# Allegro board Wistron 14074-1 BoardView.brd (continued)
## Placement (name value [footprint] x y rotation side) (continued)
R9731  0R0402-PAD-2-GP  [0R0402-PAD-1]  54.86 47.88 180 top
R9732  10KR2J-3-GP  [R402H16]  4.93 69.04 0 bottom
R9733  2K2R2J-2-GP  [R402H16]  4.93 70.94 180 bottom
R9734  2K2R2J-2-GP  [R402H16]  5.13 56.87 270 bottom
R9735  10KR2J-3-GP  [R402H16]  7.04 56.87 90 bottom
R9736  0R0402-PAD-2-GP  [0R0402-PAD-1]  24 88.14 180 top
R9737  0R2J-2-GP  [R402H16]  22.86 88.14 180 top
R9739  1KR2J-1-GP  [R402H16]  4.83 47.37 0 bottom
R9740  1KR2J-1-GP  [R402H16]  4.7 43.31 180 bottom
R9741  10KR2J-3-GP  [R402H16]  5.46 38.48 180 bottom
R9742  56D2R2F-GP  [R402H16]  135.36 139.45 0 top
R9743  56D2R2F-GP  [R402H16]  135.48 137.41 180 top
R9744  200R2F-L-GP  [R402H16]  132.21 142.27 180 bottom
R9745  200R2F-L-GP  [R402H16]  131.04 142.27 180 bottom
R9746  200R2F-L-GP  [R402H16]  39.19 69.72 270 bottom
R9751  200R2F-L-GP  [R402H16]  130.76 139.12 0 bottom
R9753  49D9R2F-GP  [R402H16]  130.07 137.59 270 bottom
R9754  49D9R2F-GP  [R402H16]  38.84 70.94 270 bottom
R9755  301R2F-GP  [R402H16]  132.21 142.62 0 top
R9756  20R2F-GP  [R402H16]  133.25 142.65 0 top
R9757  20R2F-GP  [R402H16]  37.9 65.41 90 bottom
R9761  10KR2F-2-GP  [R402H16]  182.96 64.47 270 bottom
R9762  10KR2F-2-GP  [R402H16]  189.98 68.14 90 bottom
R9764  0R0402-PAD-2-GP  [0R0402-PAD-1]  187.29 58.61 0 bottom
R9765  0R0402-PAD-2-GP  [0R0402-PAD-1]  188.33 58.61 180 bottom
R9766  10KR2F-2-GP  [R402H16]  187.62 64.53 90 bottom
R9767  10KR2F-2-GP  [R402H16]  189.73 66.05 0 bottom
R9768  10KR2F-2-GP  [R402H16]  186.14 58.64 0 bottom
R9769  10KR2F-2-GP  [R402H16]  190.74 63.39 90 bottom
R9770  10KR2F-2-GP  [R402H16]  182.85 58.65 0 bottom
R9771  10KR2F-2-GP  [R402H16]  184.84 64.47 90 bottom
R9772  0R2J-2-GP  [R402H16]  183.9 58.64 0 bottom
R9773  0R0402-PAD-2-GP  [0R0402-PAD-1]  184.91 58.64 0 bottom
R9786  100KR2J-1-GP  [R402H16]  189.52 58.61 0 bottom
R9787  0R0402-PAD-2-GP  [0R0402-PAD-1]  91.44 91.8 135 bottom
R9788  2K2R2J-2-GP  [R402H16]  5.71 115.95 0 bottom
R9789  10KR2J-3-GP  [R402H16]  6.73 115.95 0 bottom
R9790  10KR2J-3-GP  [R402H16]  6.58 109.5 270 bottom
R9792  2K2R2J-2-GP  [R402H16]  5.18 62.2 270 bottom
R9793  10KR2J-3-GP  [R402H16]  8.13 61.59 0 bottom
R9794  0R3J-0-U-GP  [R603H22]  11.78 133.26 270 top
R9795  0R3J-0-U-GP  [R603H22]  11.8 135.24 270 top
R9796  0R3J-0-U-GP  [R603H22]  11.81 139.13 270 top
R9797  0R3J-0-U-GP  [R603H22]  11.81 137.17 270 top
R9798  0R0603-PAD-2-GP-U  [0R0603-PAD-1-U]  13.57 144.24 270 top
R9799  0R0603-PAD-2-GP-U  [0R0603-PAD-1-U]  13.6 150.59 270 top
R9800  0R0603-PAD-2-GP-U  [0R0603-PAD-1-U]  21.84 134.37 270 top
R9801  0R0603-PAD-2-GP-U  [0R0603-PAD-1-U]  37.97 141.72 180 top
R9809  0R2J-2-GP  [R402H16]  180.21 146.05 270 top
R9810  0R2J-2-GP  [R402H16]  180.21 147.19 270 top
R9811  10KR2J-3-GP  [R402H16]  183.59 144.78 180 bottom
R9812  10KR2J-3-GP  [R402H16]  182.55 152.78 0 bottom
R9813  10KR2J-3-GP  [R402H16]  179.63 152.78 0 bottom
R9814  10KR2J-3-GP  [R402H16]  180.64 152.78 0 bottom
R9815  0R2J-2-GP  [R402H16]  116.52 27.73 90 bottom
R9816  0R2J-2-GP  [R402H16]  114.76 27.05 90 top
R9817  0R0402-PAD-2-GP  [0R0402-PAD-1]  45.11 122.28 180 bottom
R9818  2K2R2J-2-GP  [R402H16]  7.87 115.82 180 bottom
R9828  0R2J-2-GP  [R402H16]  21.44 33.15 90 top
R9829  0R0402-PAD-2-GP  [0R0402-PAD-1]  21.44 34.19 90 top
R9830  0R2J-2-GP  [R402H16]  22.61 28.07 180 top
R9831  0R2J-2-GP  [R402H16]  21.21 28.07 180 top
R9836  10KR2J-3-GP  [R402H16]  123.32 155.7 90 bottom
R9837  10KR2J-3-GP  [R402H16]  127 153.42 90 bottom
R9838  10KR2J-3-GP  [R402H16]  127.51 152.27 90 bottom
R9839  10KR2J-3-GP  [R402H16]  127.51 151.13 90 bottom
R9842  100KR2J-1-GP  [R402H16]  4.6 124.33 180 bottom
R9843  10KR2F-2-GP  [R402H16]  4.6 120.27 180 bottom
R9845  0R2J-2-GP  [R402H16]  16.64 13.21 0 top
R9846  1KR2J-1-GP  [R402H16]  24.94 79.25 180 top
R9847  10KR2J-3-GP  [R402H16]  26.16 84.76 270 top
R9848  2K2R2J-2-GP  [R402H16]  28.09 82.7 270 top
R9849  1KR2J-1-GP  [R402H16]  8.26 108.08 0 top
R9850  10KR2J-3-GP  [R402H16]  6.99 103.76 90 top
R9851  2K2R2J-2-GP  [R402H16]  5.08 103.76 270 top
R9852  10KR2J-3-GP  [R402H16]  95.1 76.3 135 bottom
R9853  0R2J-2-GP  [R402H16]  24.94 81.15 180 top
R9854  0R2J-2-GP  [R402H16]  8.26 106.17 0 top
R9855  1KR2J-1-GP  [R402H16]  91.39 85.1 90 bottom
R9857  0R0402-PAD-2-GP  [0R0402-PAD-1]  26.16 83.74 270 top
R9858  0R2J-2-GP  [R402H16]  26.16 82.73 270 top
R9859  1KR2J-1-GP  [R402H16]  44.2 127.74 180 bottom
R9861  10KR2J-3-GP  [R402H16]  27.61 84.15 180 top
R9863  150R2F-1-GP  [R402H16]  117.09 102.64 135 bottom
R9864  10KR2J-3-GP  [R402H16]  112.27 111.25 225 top
R9866  0R2J-2-GP  [R402H16]  177.8 145.16 0 top
R9867  20KR2J-L2-GP  [R402H16]  101.45 117.91 315 top
R9872  2K2R2J-2-GP  [R402H16]  7.75 71.12 90 bottom
R9873  200R2F-L-GP  [R402H16]  39.12 67.46 270 bottom
R9874  301R2F-GP  [R402H16]  39.12 66.45 270 bottom
R9875  0R0402-PAD-2-GP  [0R0402-PAD-1]  134.34 142.65 180 top
R9876  0R0402-PAD-2-GP  [0R0402-PAD-1]  131.5 144.22 270 top
R9879  10KR2J-3-GP  [R402H16]  176.81 143.59 180 bottom
R9882  8K2R2J-3-GP  [R402H16]  98.53 31.14 270 bottom
R9884  0R2J-2-GP  [R402H16]  31.62 12.95 270 top
RN801  SRN2K2J-1-GP  [ARES2H16]  159 149.99 270 top
RN1501  SRN2K2J-1-GP  [ARES2H16]  157.96 127.38 270 bottom
RN1502  SRN2K2J-1-GP  [ARES2H16]  33.37 140.75 270 top
RN1503  SRN2K2J-1-GP  [ARES2H16]  174.75 145.03 90 bottom
RN1901  SRN2K2J-1-GP  [ARES2H16]  27.79 86.54 270 top
RN1902  SRN2K2J-1-GP  [ARES2H16]  49.02 124.97 180 bottom
RN1903  SRN2K2J-1-GP  [ARES2H16]  80.14 41.12 180 top
RN2501  SRN4K7J-8-GP  [SMD-ARES4H18]  77.08 49.46 90 bottom
RN2502  SRN4K7J-8-GP  [SMD-ARES4H18]  77.05 51.51 90 bottom
RN3601  SRN2K2J-5-GP  [SMD-ARES4H18]  48.24 102.07 90 top
RN5402  SRN2K2J-1-GP  [ARES2H16]  134.82 150.67 0 top
RN5404  SRN2K2J-5-GP  [SMD-ARES4H18]  45.67 101.68 0 top
RN5407  SRN2K2J-1-GP  [ARES2H16]  8.64 54.36 180 bottom
RN5408  SRN10KJ-5-GP  [ARES2H18]  8.15 58.95 0 bottom
RN5409  SRN2K2J-1-GP  [ARES2H16]  8.38 64.64 0 bottom
RN5410  SRN10KJ-6-GP  [ARES8-CN24-MUH20]  109.04 18.92 0 bottom
RN5411  SRN2K2J-1-GP  [ARES2H16]  66.1 125.21 0 bottom
RN5601  SRN1KJ-7-GP  [SMD-ARES4H18]  155.96 147.96 270 top
RN5602  SRN1KJ-7-GP  [SMD-ARES4H18]  159 147.96 90 top
RN5603  SRN1KJ-7-GP  [SMD-ARES4H18]  124.51 152.02 270 bottom
RN5604  SRN1KJ-7-GP  [SMD-ARES4H18]  124.51 154.03 270 bottom
RN6102  SRN0J-6-GP  [SMD-ARES4H20]  28.07 113.54 0 bottom
RN6401  SRN1KJ-7-GP  [SMD-ARES4H18]  8.69 26.04 0 bottom
RN9901  SRN0J-6-GP  [SMD-ARES4H20]  192.15 119.38 0 bottom
SATA0  SKT-SATA7P-19-GP-U  [ABA-SAT-010-K04-U]  55 13 90 top
SATA1  SKT-SATA7P-19-GP-U  [ABA-SAT-010-K04-U]  64.45 13 90 top
SATAP1  JWT-CON6-3-GP  [A2501WV2-6P]  24.15 45.76 270 top
SIO1  IT8772E-EX-GP  [LQFP64H63]  106.81 28.03 180 bottom
SPI1  SKT-SPI8P-GP-U1  [SKT-SOIC8-092117H235]  75.93 52.5 0 top
SPIH1  PIN-CON3-S-GP  [21S-91-03GB01]  73.71 38.63 90 top
TC1901  E220U16VM-25-GP  [ECAP-100D6D3H473]  26.42 126.54 0 top
TC2201  SC10U6D3V3MX-GP  [C603H38]  28.5 155.22 0 top
TC2202  SC10U6D3V3MX-GP  [C603H38]  26.41 155.24 0 top
TC2203  E100U16VM-25-GP  [ECAP-80D5H493]  5.41 152.48 90 top
TC2204  E100U16VM-25-GP  [ECAP-80D5H493]  9.48 146.64 90 top
TC2501  E220U16VM-25-GP  [ECAP-100D6D3H473]  189.59 32.05 90 top
TC2701  E100U16VM-25-GP  [ECAP-80D5H493]  37.21 146.56 90 top
TC2702  SC10U6D3V3MX-GP  [C603H38]  27.23 162.02 90 top
TC2703  SC10U6D3V3MX-GP  [C603H38]  27.24 163.97 90 top
TC2704  E100U16VM-25-GP  [ECAP-80D5H493]  30.61 146.56 90 top
TC2705  SC10U6D3V3MX-GP  [C603H38]  27.24 158.12 90 top
TC2706  SC10U6D3V3MX-GP  [C603H38]  27.24 160.07 90 top
TC4601  SC10U10V5KX-2GP  [C805H54]  36.47 110.39 90 bottom
TC4602  E220U16VM-25-GP  [ECAP-100D6D3H473]  92.58 146.18 0 top
TC4603  E220U16VM-25-GP  [ECAP-100D6D3H473]  33.47 29.59 0 top
TC4606  E220U16VM-25-GP  [ECAP-100D6D3H473]  106.81 144.17 0 top
TP2401  -  [TPAD28]  112.9 28.32 180 bottom
TP2402  -  [TPAD28]  114.33 27.37 180 bottom
TP9601  TPAD14-OP-GP  [TPAD14-OP]  190.12 104.62 0 bottom
TP9602  TPAD14-OP-GP  [TPAD14-OP]  190.12 105.89 0 bottom
TP9905  -  [TPAD24]  137.34 89.15 0 top
TP9906  -  [TPAD24]  90.42 92.35 0 top
TXE1  PIN-CON3-S-GP  [21S-91-03GB01]  175.69 133.19 270 top
U3RJ1  SKT-RJ45-USB-83-GP  [PU2B1B5-PRTB]  76.9 163.99 180 top
U2402  G2129TL1U-GP  [SC70-6H44]  116.21 35.14 270 bottom
U2502  W25Q64FWSSIG-GP  [SOIC8-1H86]  75.93 52.5 180 top
U2901  GS7605ST-R-GP  [SOT23-8PH36]  25.5 30.35 270 top
U2903  GS7605ST-R-GP  [SOT23-8PH36]  25.4 34.54 270 top
U3701  SY6288CAAC-GP  [SOT-23-5H56]  25.4 34.29 270 bottom
U3702  SY6288CAAC-GP  [SOT-23-5H56]  107.92 150.42 0 top
U3703  SY6288CAAC-GP  [SOT-23-5H56]  25.53 30.48 270 bottom
U3801  SY6288CAAC-GP  [SOT-23-5H56]  113.03 154.43 270 bottom
U4301  AO4468L-GP  [SOIC8H69]  173.61 17.91 270 top
U4601  GL850G-OHY31-GP  [QFN28-G3D75H32]  42.57 101.48 90 bottom
U4602  M24C02-WMN6TP-1-GP  [SOIC8H69]  42.42 112.98 0 bottom
U5401  TPS22966DPUR-GP  [SON14J3020-G2610H34]  158.35 19.91 270 top
U6506  RTD2168-CGT-GP  [QFN32-G3D6H40]  174.68 149.79 270 top
U6510  GS7605ST-R-GP  [SOT23-8PH36]  119.89 156.21 270 bottom
U6511  GS7605ST-R-GP  [SOT23-8PH36]  118.62 152.27 270 bottom
U6519  M24128-BWMN6TP-GP  [SOIC8H69]  165.2 149.63 180 top
U6523  2N7002KDW-1-GP  [SOT-363H44]  188.2 62.13 0 bottom
U6524  2N7002KDW-1-GP  [SOT-363H44]  184.01 62.13 0 bottom
UART1  JOWLE-CON2-5-GP  [A2541WV0-1EX2PA-6T]  73.73 31.45 270 top
USB2F1  PIN-CON5-SFP2-GP-U  [210-91-05GY21-U]  47.5 11 270 top
USB2F2  JWT-CONN10D-SFP10-GP  [A2541WV0-2AX5PA-6T-K]  34.37 45.26 90 top
USB2R1  SKT-USB12-24-GP  [SKT-USB12-157183]  99.4 160.72 180 top
USB3F1  LOTES-CONN20C-SFP1-GP  [ABA-USB-050-K07]  41.5 36 90 top
VGA1  D-SUB-15-154-GP  [DZ11AA1-H5W7-4F]  166 166 0 top
X1501  XTAL-19D2MHZ-12-GP  [OSC-3225-4P-4H30]  94.33 101.48 45 top
X2101  XTAL-25MHZ-181-GP  [OSC-3225-4P-4H36]  60.47 119.92 90 top
X3501  XTAL-12MHZ-67-GP  [OSC-3225-4P-4H36]  47.47 97.44 270 top
X3502  XTAL-32D768KHZ-64-GP  [SMD49-6914-0403H56]  89.12 98.03 135 top
XDP1  SMC-CONN60A-GP  [BSH-03001-FDA]  186.99 105.03 90 bottom

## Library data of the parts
ATX1 = C4201WV0-B2X12P: tolerance: 21.70163.212
ATX2 = PPA12635GD210F: tolerance: 20.80334.020
AUDH1 = 1E450400: tolerance: 21.62868.205
AUDIO1 = PFPCC48-1H63: tolerance: 71.00662.00G
AUDR1 = ABA-JAK-028-K03: tolerance: 22.10251.831
BT1 = AAA-BAT-029-K01: tolerance: 22.70034.011
BUZ1 = AC-1205G-N1LF-U: tolerance: 23.60026.001
C20 C501-C504 C1217 C1218 C1225 C1226 C1315 C1317 C1318 C1325 C1326 C1801 C1802 C1903 C1905-C1913 C2002 C2006 C2009 C2011-C2014 C2016 C2019 C2020 C2103-C2105 C2107-C2111 C2115 C2201 C2203 C2205 C2207 C2208 C2211 C2215-C2217 C2219 C2301 C2415 C2434 C2435 C2501 C2507 C2709 C2813 C3402 C3405 C3407 C3408 C3410 C3501 C3508 C3509 C4601 C4605 C4606 C4608 C4610 C5401-C5410 C7542 C9602-C9604 C9606 C15110 C15112-C15127 C15141-C15146 C15149-C15152 C15154 C15155 C15157 C15163-C15167 C15170-C15175 C15186 C15188 C15191 C15192 EC3401 EC3412-EC3414 PC3602 PC4202 PC4203 PC4410 PC4416 PC4428 PC4510 PC4516 PC4528 PC4701 PC4707 PC4803 PC4808 PC5003 PC5029 PC5032 PC5103 PC5109 PC5212 PC5218 PC5219 = C402H22: tolerance: 78.10421.2FL
C1001-C1008 C1013 C1017 C1018 C1020 C1022 C1024-C1027 C1030 C1032-C1035 C1037 C1047 C1056 C1057 C1102 C1103 C1105 C1108 C1110 C1111 C1113 C1115 C1116 C1118 C1119 C1121 C1126-C1128 C1132-C1134 C1137 C1138 C1209-C1216 C1219-C1222 C1309-C1314 C1316 C1319-C1322 C2003 C2008 C2017 C2040 C2114 C2503 C2912 C3502 C3505 C4602 C4607 C4609 C5416 C5418 C15111 C15185 C15187 C15189 C15190 PC4422 PC4522 PC4702 PC4802 PC4909 PC4910 PC4926 PC5028 PC5034 PC5035 PC5104 PC5112 PC5213 = C402H22: tolerance: 78.10523.5FL
C1009-C1012 C1040-C1042 C1048 C1104 C1114 C1120 C1122-C1124 C1130 C2707 C5413 C5415 C5417 C5419 = C603H40: tolerance: 78.22610.5BL
C1031 C1043-C1046 C1049 C1201-C1208 C1223 C1224 C1230 C1231 C1301-C1308 C1323 C1324 C1330 C1331 C2506 C6102 C15147 C15148 PC4708 PC4804 PC4806 PC4807 PC5031 PC5108 PC5214 PC5216 PC5217 TC2201 TC2202 TC2702 TC2703 TC2705 TC2706 = C603H38: tolerance: 78.10610.5BL
C1227 C1327 C2229 C2907 C2908 C3301 C3302 C3403 PC4413 PC4418 PC4429 PC4513 PC4518 PC4529 PC4704 PC5005 PC5041 = C402H22: tolerance: 78.10224.2FL
C1412 C1413 C1417-C1422 C4303 PC4427 PC4527 PC4922 PC4923 PC4925 PC5002 = C402H22: tolerance: 78.10324.2FL
C1501 C1502 = C402H22: tolerance: 78.6R874.1FL
C1803 C2206 EC7615-EC7617 PC4705 PC4805 PC5107 PC5215 = C402H22: tolerance: 78.22034.1FL
C1901 C1902 C2015 C2018 C2101 C2708 C2809-C2811 C2903 C2911 C3411 C3416 C5601-C5604 C15129 C15183 C15184 EC3409 = C402H22: tolerance: 78.10491.4FL
C2001 C2005 C2227 C2228 C2230 C2231 C2701-C2706 C5303 C5306 EC2314 EC2323 EC7612 EC7613 PC4206 = C402H22: tolerance: 78.10134.1FL
C2004 C2102 C2106 C3404 = C402-TO0D2H26: tolerance: 78.47510.5FL
C2010 C3504 C3506 C3507 = C603H36: tolerance: 78.10593.4BL
C2116 C2117 = C402H22: tolerance: 78.15034.1FL
C2119 C2120 PC4914 PC4918 = C603H36: tolerance: 78.47520.5BL
C2202 C2204 PC3601 PC3603 = C805H54: tolerance: 78.10693.41L
C2209 C2212 C2218 C2220 TC4601 = C805H54: tolerance: 78.10623.51L
C2210 EC2501-EC2503 = C402H22: tolerance: 78.4R774.1FL
C2303 PC4417 PC4419 PC4517 PC4519 = C402H22: tolerance: 78.47124.2FL
C3406 = C402H22: tolerance: 78.10322.2FL
C4301 C6001 C6002 PC4201 PC4908 PC4921 PC4927 PC5004 = C603H36: tolerance: 78.10422.2BL
C4302 C5001 C5411 EC4101 PC4204 PC4703 PC5011 PC5040 PC5105 = C603H36: tolerance: 78.10424.2BL
C4603 C4604 = C402H24: tolerance: 78.12034.1FL
C4611 = C603H36: tolerance: 78.10421.2BL
C5301 C5307-C5311 = C402H22: tolerance: 78.4R7B4.1FL
C5304 C5305 = C402H22: tolerance: 78.18034.1FL
C5412 C5414 = C402H22: tolerance: 78.10224.L1L
C6003 C6004 PC4424 PC4431 PC4524 PC4531 PC4706 PC4711 PC5038 PC5039 PC5101 PC5102 = C805H56: tolerance: 78.10622.51L
C6101 C6103 C6104 = C402H22: tolerance: 78.10422.2FL
C6105 = C402H22: tolerance: 78.10034.1FL
C7537 C7539 = C402H22: tolerance: 78.10523.L2L
C7538 C7540 = C402H22: tolerance: 78.7R064.1FL
C7924 EC4102 PC4423 PC4523 = C402H22: tolerance: 78.10422.5FL
C9605 PC5036 PC5037 = C402H22: tolerance: 78.10423.2FL
C15153 C15156 PC4426 PC4526 = C603H36: tolerance: 78.22523.5BL
C15178 PC4801 PC5211 PC5220-PC5222 = C402H20: tolerance: 78.10423.5FL
CMOS1 SPIH1 TXE1 = 21S-91-03GB01: tolerance: 21.61445.103
CPU1 = BGA1170M2725H57: tolerance: 071.BRASW.000U
D3 D4 = SOT-23-9H44: tolerance: 83.00056.Q11
D1501 = SOT23-2D4-312H44: tolerance: 75.00054.T7D
D2101 D2402 D2502 D3401 = SOD323AKH40: tolerance: 83.00355.F1F
D2201 D2203 = SOT-23-10H44: tolerance: 83.00054.R81
D2202 D2701-D2703 = D1608AK-UH28: tolerance: 83.0DF2B.0AF
D2704-D2706 = SOT23-2D4-312H46: tolerance: 75.05125.07D
D3402-D3404 = SOT23-2D4-312H48: tolerance: 75.00054.R7D
DBGH1 = 220-47-07GB22: tolerance: 21.62888.207
DCIN1 = 2DC-G726-Q15: tolerance: 22.10037.K01
DIMM1 = AAA-DDR-109-P06: tolerance: 62.10017.W31
DIMM2 = 1932208-1: tolerance: 62.10024.P91
DIMM3 = 1932210-1: tolerance: 62.10017.N61
EC2801-EC2808 = C402H22: tolerance: 78.1R574.1FL
ED2 ED2303 ED2304 ED2801 ED2802 ED2804 ED2907 ED3203 ED6512 ED6520 ED6521 = SOT-6H58: tolerance: 75.09904.07C
ED2301 ED2302 ED2305-ED2308 ED6513 ED6514 = DFN10G2510H26: tolerance: 75.01045.073
ED3201 ED3202 = SOD882-10D6-1H20: tolerance: 83.05725.0A0
ED4101 = D5436AKH97: tolerance: 83.P6SBM.AAG
EL5314 EL5324-EL5326 EL5328 EL5330-EL5336 = L125100-4P-5H24: tolerance: 68.24500.201
EL5316-EL5318 EL5337 = L125100-4P-4H24: tolerance: 68.00396.001; signal model: L125100-4P-4H24_COIL-90OHM-100MHZ-5-GP
EL5321-EL5323 EL5327 EL5329 EL5609 EL5610 = L125100-4P-4H24: tolerance: 68.00396.001
EL5601-EL5608 = L125100-4P-1H28: tolerance: 68.10129.201
F2301 F2402 = POLYSW-2114H30: tolerance: 69.48001.081
FANC1 = A2543WV2-3P: tolerance: 20.60333.103
FANC2 = HF1004E: tolerance: 21.60626.104
G1 PR4225 PR4410 PR4413 PR4510 PR4513 PR5035 PR9742 PR9757 R1206 R1207 R1216 R1306 R1307 R1316 R1804 R1806 R1905 R1907 R1909 R1937 R2007 R2015 R2101-R2104 R2225 R2228 R2519 R2522 R3404 R3406 R3528 R4302 R6104 R6108 R6109 R6801 R6802 R9605 R9608 R9613 R9621 R9622 R9628 R9629 R9703 R9708 R9709 R9728 R9729 R9731 R9736 R9764 R9765 R9773 R9787 R9817 R9829 R9857 R9875 R9876 = 0R0402-PAD-1: tolerance: ZZ.00PAD.M11
G1901 G1902 = CON2O-U: tolerance: ZZ.CON2O.XXX
GPIO1 GPIO2 UART1 = A2541WV0-1EX2PA-6T: tolerance: 21.60909.102
H3301-H3304 = GENS315R158-8-F-A: tolerance: ZZ.SCREW.541
HDMI1 HDMI2 = SKT-HDMI23-150122-9: tolerance: 62.10078.641
HNGFF1 = STF256R109H99: tolerance: 34.3NH01.001
L2101 = L3030-3009-2H40: tolerance: 68.4R71G.10G
L2202 L3401 L5305 L5311-L5313 = L603H38: tolerance: 68.00335.091
L2701-L2706 PR4706 PR4802 PR5027 PR5034 PR5108 PR5109 PR5209 PR5215-PR5225 R6103 R9699 R9798-R9801 = 0R0603-PAD-1-U: tolerance: ZZ.00PAD.M21
L5301-L5303 = L603H38: tolerance: 68.00245.051
LAN1 = QFN32J4-G2D85H36: tolerance: 71.08111.U03
LEDH1 = T11-0063-1A40-0-U: tolerance: 21.62738.207
NGFFE1 = AS0BC21-S40BE-7H: tolerance: 062.10003.0611
OSC1 = SMD-OSC8H52: tolerance: 82.20013.151
PC3604 TC1901 TC2501 TC4602 TC4603 TC4606 = ECAP-100D6D3H473: tolerance: 09.2271D.X8L
PC4205 = C805H58: tolerance: 78.10594.41L
PC4409 PC4509 = C402H22: tolerance: 78.10413.5FL
PC4411 PC4511 = C402H22: tolerance: 78.33124.2FL
PC4412 PC4512 = C402H22: tolerance: 78.47034.1FL
PC4414 PC4514 = C402H22: tolerance: 78.10232.2FL
PC4415 PC4515 = C402H22: tolerance: 78.33224.2FL
PC4420 PC4520 = C402H22: tolerance: 78.68124.2FL
PC4421 PC4521 PC5008 = C603H40: tolerance: 78.22422.2BL
PC4911 PC4913 = C402H22: tolerance: 78.22034.1FLLL
PC4912 PC5009 PC5010 = C603H36: tolerance: 78.10521.5BL
PC4915 PC4916 PC5001 = C603: tolerance: 78.15224.2BL
PC4917 = C402H22: tolerance: 78.18034.1FLLL
PC4919 PC4920 PC4924 PC5007 PC5012 = C805H54: tolerance: 78.47522.51L
PC5006 = C402H22: tolerance: 78.10321.2FLLL
PC5030 = C402H22: tolerance: 78.33321.2FL
PC5033 = C603H38: tolerance: 78.10620.5BL
PC5106 = C603H36: tolerance: 78.10224.2BL
PC5110 PC5111 = C402H22: tolerance: 78.10520.5FL
PCIE16 = 2EG38217-D2D-4F: tolerance: 20.50441.164
PD5001 = SOD323AKH38: tolerance: 83.R5003.H8H
PG4401 PG4402 PG4501 PG4502 = CON2C: tolerance: ZZ.CON2C.XX1
PG4901-PG4904 = GAP-CLOSE-PWR-3: tolerance: ZZ.CLOSE.001
PL4401 PL4501 = L686647-127318H119: tolerance: 68.R3310.10D
PL4402 PL4403 PL4502 PL4601 PL4702 PL4703 PL4801 PL4901 PL4902 PL5002-PL5004 PL5006 PL5007 PL5102 PL5103 = L603H38: tolerance: 68.00335.181
PL4701 PL5001 = L686647-127318H119: tolerance: 68.R8210.10Z
PL4903 PL4904 = L686647-127318H119: tolerance: 68.3R31A.10V
PL5005 = L686647-127318H119: tolerance: 68.5R610.10U
PL5101 = L686647-127318H119: tolerance: 68.2R21B.10J
PN4401 PN4402 PN4501 PN4502 = NTC-402H24-U: tolerance: 69.60028.041
PQ4401 PQ4501 PQ4701 PQ5001 = PPAK-8P-5262H40: tolerance: 84.06520.037
PQ4402 PQ4502 PQ4702 PQ5002 = PPAK-8P-5262H40: tolerance: 084.06510.0037
PQ4901 PQ4903 PQ5003 = PPAK-8P-3030H40: tolerance: 084.03319.0037
PQ4902 PQ4904 PQ5004 = PPAK-8P-3030H40: tolerance: 084.03317.0037
PQ5005 Q3409 Q4001 Q4101 Q4303 Q6528 Q6542 Q6543 U6523 U6524 = SOT-363H44: tolerance: 75.27002.F7C
PQ5101 PQ5102 = PPAK-8P-3232H40: tolerance: 084.03319.0A37
PR3601 = R402H16: tolerance: 64.12405.6DL
PR3602 = R402H16: tolerance: 64.21005.6DL
PR4201 PR4205 PR4219 PR4515 = R402H16: tolerance: 64.30025.6DL
PR4202 = R402H16: tolerance: 64.39005.6DL
PR4203 = R402H16: tolerance: 64.82015.6DL
PR4204 PR4206 PR4218 = R402H16: tolerance: 64.30035.6DL
PR4207 PR4208 PR4210 PR4223 PR4920 R2008 R2109 = R402H16: tolerance: 64.15025.6DL
PR4209 PR4213 PR5110 = R402H16: tolerance: 64.10035.6DL
PR4211 PR4212 R1918 R1919 R1930 R2518 R4004 R9674 R9867 = R402H16: tolerance: 63.20334.1DL
PR4214 R1530 = R402H16: tolerance: 64.20035.6DL
PR4215 PR4922 PR4925 PR5032 R1505 R1527-R1529 R1540 R1912 R2515 R3516 R3521 R4003 R4304 R4306 R4607 R5403 R6542 R9702 R9786 R9842 = R402H16: tolerance: 63.10434.1DL
PR4216 PR4222 PR4431 R507-R510 R1542 R1603 R1901 R1904 R1906 R1908 R1911 R2026 R2110 R2115 R2130 R2204 R2412 R2413 R3529 R4001 R4002 R4609 R4610 R5004 R5601 R5602 R6106 R6107 R6110 R6526-R6529 R6532 R6533 R6556 R6557 R6562 R6803 R6804 R9645 R9704 R9730 R9737 R9772 R9809 R9810 R9815 R9816 R9828 R9830 R9831 R9845 R9853 R9854 R9858 R9866 R9884 = R402H16: tolerance: 63.R0034.1DL
PR4217 = R2512-1U1H36: tolerance: 64.R1005.97L
PR4220 PR4221 PR4224 PR4226 PR4423 PR4523 PR4904 PR4905 R2107 R9705 = R805H24: tolerance: 63.R0031.16L
PR4401 PR4429 PR4434 PR4501 PR4529 PR4601 R1533 R1915 R1920 R2016 R2033 R2034 R2038 R2049 R2220 R2221 R2475 R2701 R2704 R2705 R2708 R2711 R2714 R2716 R2718 R2719 R2723 R2725 R2726 R2732 R2734 R3501 R3517 R3518 R4305 R9604 R9607 R9660 R9662 R9671 R9672 R9739 R9740 R9846 R9849 R9855 R9859 = R402H16: tolerance: 63.10234.1DL
PR4404 PR4504 = R402H16: tolerance: 64.47R05.6DL
PR4405 PR4505 R2108 = R402H16: tolerance: 64.10015.6DL
PR4406 PR4506 = R402H16: tolerance: 64.56035.6DL
PR4407 PR4507 PR5003 = R402H16: tolerance: 64.33015.6DL
PR4408 PR4409 PR9764-PR9766 R2050 R2513 R6401-R6403 = R402H14: tolerance: 63.10134.1DL
PR4411 PR4511 = R402H16: tolerance: 64.15015.6DL
PR4414 PR4514 = R402H16: tolerance: 64.62025.6DL
PR4415 = R402H16: tolerance: 64.34025.6DL
PR4416 PR4516 R6566 R6568 R6570-R6572 = R402H14: tolerance: 63.10034.1DL
PR4417 PR4517 = R603H22: tolerance: 64.10035.55L
PR4418 R503-R506 R511-R514 R1202 R1203 R1210 R1211 R1304 R1305 R1310 R1311 R1501 R1502 R1524 R1541 R4005 R9648-R9657 = R402H16: tolerance: 64.47015.6DL
PR4419 PR4519 = R402H16: tolerance: 64.75025.6DL
PR4420 PR4520 = R402H16: tolerance: 64.15035.6DL
PR4421 PR4424 PR4430 PR4521 PR4524 PR4530 PR4713 PR4714 PR4716 PR4903 PR4911 PR4912 PR4926 PR5001 PR5010 PR5011 PR5013 PR5029 PR5037 PR5105 PR5106 PR5117 = R805H24: tolerance: 63.2R231.16L
PR4422 PR4522 PR4715 PR5015 PR5016 PR5103 PR5229 PR5232-PR5234 PR9763 R1201 R1204 R1205 R1208 R1209 R1301-R1303 R1308 R1309 R1515 R1632 R1634 R1801 R1802 R1807 R1933 R1936 R1945 R2004 R2022 R2025 R2027 R2028 R2036 R2037 R2041 R2045 R2047 R2048 R2051 R2112 R2113 R2203 R2223 R2474 R2508 R2514 R2720 R2721 R2733 R3202 R3403 R3405 R3407 R3409 R3411 R3522 R3524 R3527 R3701-R3704 R4503 R4602 R4604 R4605 R4608 R5001-R5003 R5401 R6101 R6102 R6519 R6520 R6534 R6535 R6558 R6559 R6574 R9606 R9611 R9643 R9675 R9725 R9732 R9735 R9741 R9789 R9790 R9793 R9811-R9814 R9836-R9839 R9847 R9850 R9852 R9861 R9864 R9879 = R402H16: tolerance: 63.10334.1DL
PR4426 PR4526 = R402H16: tolerance: 64.54R95.6DL
PR4427 PR4527 PR5004 R6508-R6512 = R402H16: tolerance: 64.75R05.6DL
PR4428 PR4528 = R603H22: tolerance: 63.1R033.15L
PR4432 = R402H16: tolerance: 64.22025.6DL
PR4433 PR4533 R2908 R2910 = R402H16: tolerance: 64.18725.6DL
PR4518 PR4718 PR4803 PR4916 PR4919 PR4921 PR5012 PR5102 PR5211 R1503 R1504 R1507-R1513 R1516-R1520 R1522 R1523 R1525 R1526 R1602 R2001-R2003 R2010 R2014 R2018 R2019 R2054 R2206 R3502 R3525 R3526 R4006 R6105 R6404 R6507 R6564 R6565 R9761 R9762 R9766-R9771 R9843 = R402H16: tolerance: 64.10025.6DL
PR4531 = R402H16: tolerance: 64.48725.6DL
PR4532 = R402H16: tolerance: 64.53625.6DL
PR4701 PR5024 PR5104 = R402H16: tolerance: 63.5R134.1DL
PR4702 PR5116 = R402H16: tolerance: 64.47035.6DL
PR4711 PR4918 = R402H16: tolerance: 64.68025.6DL
PR4712 PR4805 PR5115 PR5231 R1226 R2029 R2043 R2501 R2510 R2712 R2717 R2730 R3420 R6573 R9661 R9663 R9664 R9733 R9734 R9788 R9792 R9818 R9848 R9851 R9872 = R402H16: tolerance: 63.22234.1DL
PR4717 = R402H16: tolerance: 64.51115.6DL
PR4720 PR4820 PR5120 PR5240 = R402H16: tolerance: 63.33234.1DL
PR4801 PR4804 PR4906-PR4910 PR4913 PR4915 PR5007-PR5009 PR5025 PR5026 PR5028 PR5033 PR5036 PR5038 PR5210 PR5213 R4601 = 0R0805-PAD-1-U: tolerance: ZZ.00PAD.M31
PR4806 = R402H16: tolerance: 64.44215.6DL
PR4914 = R402H16: tolerance: 64.66515.6DL
PR4917 = R402H16: tolerance: 64.21525.6DL
PR4923 = R402H16: tolerance: 64.12735.6DL
PR4924 = R402H16: tolerance: 64.13035.6DL
PR5002 = R402H16: tolerance: 64.16025.6DL
PR5005 PR5018 = R402H16: tolerance: 64.22115.6DL
PR5006 PR5017 = R402H16: tolerance: 64.15805.6DL
PR5014 = R805H24: tolerance: 63.4R731.16L
PR5023 = R402H16: tolerance: 64.88715.6DL
PR5030 = R603H22: tolerance: 63.2R233.15L
PR5031 = R402H16: tolerance: 64.62035.6DL
PR5041 = R402H16: tolerance: 64.80615.6DL
PR5101 = R402H16: tolerance: 64.15825.6DL
PR5107 = R402H16: tolerance: 64.19635.6DL
PR5214 = R402H16: tolerance: 64.54915.6DL
PR9758 PR9759 R2811 = R402H16: tolerance: 63.20134.1DL
PT4401-PT4403 PT4501-PT4504 PT4701 PT5001 PT5002 PT5102 = ECAP-100D6D3H375: tolerance: 09.8271V.08L
PT4491 PT4591 = ECAP-138D8-UH355: tolerance: 09.2771D.C8L
PT4702 PT5003 PT5101 = ECAP-100D6D3H375: tolerance: 09.56710.A8L
PT4901 = CT7343H83: tolerance: 79.15612.20L
PT4902 PT4903 = SE361416H178: tolerance: 77.52271.09L
PT5004 = SE361414H241: tolerance: 79.47612.3GL
PT5005 = ECAP-100D6D3H237: tolerance: 09.1071D.F5L
PU3601 = SMD-TO-252-4H100: tolerance: 074.01085.003M
PU4201 = SOIC8H69: tolerance: 84.04407.G37
PU4202 PU4203 = SOIC8H69: tolerance: 74.00358.K11
PU4401 PU4501 = LFQFN28J4-G2D7-UH40: tolerance: 074.81201.0073
PU4701 PU5101 = DFN10G3-G265175H32: tolerance: 74.08237.B73
PU4801 PU5202 = SOIC8-G3530H63: tolerance: 74.05930.B3D
PU4902 = QFN20-G1D75H32: tolerance: 74.08243.073
PU5001 = LFDFN10G3-G2619H40: tolerance: 74.01589.073
PU5004 = QFN20-G1D75H32: tolerance: 74.08207.C73
PU5102 = SOT-23-5H52: tolerance: 74.01339.B3F
Q1906 Q2503 Q6504 Q6532 Q6539 Q6546-Q6549 Q6551-Q6553 = SOT23CBE2D4H44: tolerance: 84.T3904.H11
Q2001 Q3403 Q3512 Q3514 Q3516 Q4304 Q6502 Q6503 Q6510 Q6512 Q6514 Q6519 Q6520 Q6527 Q6544 Q6550 = SOT23DGS2D4H44: tolerance: 84.27002.Z31
Q2501 Q2502 Q2706 Q2707 Q2709 Q3401 Q3404 Q4301 = SOT23CBE2D4H44: tolerance: 84.T3906.A11
Q2701-Q2705 Q6530 Q6531 Q6533 Q6540 Q6541 = SOT-363H44: tolerance: 75.03904.B7C
Q2711 Q2712 Q3402 = SOT23CBE2D4H44: tolerance: 84.T3904.C11
Q3507 = SMD-TO-252-DGS6698H99: tolerance: 84.03004.036
Q3508-Q3511 Q6545 = SOT23DGS2D8H50: tolerance: 84.03413.B31
Q4201 Q5401 = SOT23DGS2D4H48: tolerance: 84.2N702.E31
Q4202 Q4302 = SOT-363H44: tolerance: 84.2N702.A3F
Q6509 Q6511 Q6515-Q6518 = SOT23DGS2D4H48: tolerance: 84.05067.031
R1 R2 R9689 R9690 = R402H16: tolerance: 63.20234.1DL
R501 R502 = R402H16: tolerance: 64.18205.6DL
R801 R802 R1803 R1805 R6563 = R402H16: tolerance: 64.40205.6DL
R804 R1536 R1935 = R402H14: tolerance: 64.10005.6DL
R809 = R402H16: tolerance: 64.80R65.6DL
R1534 R2106 = R402H16: tolerance: 64.24915.6DL
R1535 R6560 R9753 R9754 = R402H16: tolerance: 64.49R95.6DL
R1601 = R402H16: tolerance: 64.40225.6DL
R1902 R1903 R1910 R2011 R3410 R6567 R9707 = R402H16: tolerance: 63.33034.1DL
R1917 R2114 = R402H16: tolerance: 63.10634.1DL
R1938 R1940 R1942-R1944 R9620 = R402H16: tolerance: 63.51034.1DL
R2005 = R402H16: tolerance: 64.20015.6DL
R2013 = R402H16: tolerance: 64.64915.6DL
R2020 R2021 = NTC-402H22-U: tolerance: 69.60011.121
R2024 R2042 R2046 R2057 R2214 R2218 R2226 R2229 R2414 R2415 R2511 R2512 R2517 R3415 R4307 = R402H16: tolerance: 63.47234.1DL
R2030-R2032 R2035 R2520 R9882 = R402H16: tolerance: 63.82234.1DL
R2056 R2801 R2810 R2813 R2814 = R402H16: tolerance: 63.33134.1DL
R2105 = R402H16: tolerance: 63.30134.1DL
R2121 R4606 = R402H16: tolerance: 64.68005.6DL
R2205 = R402H16: tolerance: 64.51015.6DL
R2207 R2208 R2213 = R402H16: tolerance: 64.20025.6DL
R2209 = R402H16: tolerance: 64.39225.6DL
R2222 R2224 R2702 R2703 R2706 R2707 R2713 R2715 = R402H16: tolerance: 63.75034.1DL
R2230 R2231 R2709 R2710 R3413 R3414 R3418 R3419 R4301 = R402H16: tolerance: 63.22334.1DL
R2418-R2420 R9863 = R402H16: tolerance: 64.15005.6DL
R2509 R3519 R3520 R5801 R9644 R9794-R9797 = R603H22: tolerance: 63.00000.00L
R2516 = R402H16: tolerance: 64.33005.6DL
R2722 = R402H16: tolerance: 63.22434.1DL
R2729 R2731 = R603H22: tolerance: 63.75033.15L
R2903 R2904 = R402H16: tolerance: 64.32425.6DL
R3402 R3416 = R603H22: tolerance: 63.91033.15L
R3422 = R805H24: tolerance: 63.22133.16L
R3423-R3425 = R805H24: tolerance: 63.10133.16L
R3523 = R402H16: tolerance: 63.27234.1DL
R4303 = R402H16: tolerance: 63.33434.1DL
R4308 = R805H24: tolerance: 63.30131.16L
R4603 = R402H16: tolerance: 63.47334.1DL
R4611-R4614 = R402H16: tolerance: 63.30334.1DL
R5603-R5610 = R402H16: tolerance: 63.18134.1DL
R6561 = R402H16: tolerance: 64.11305.6DL
R9647 = R402H16: tolerance: 63.12334.1DL
R9658 R9659 = R402H16: tolerance: 63.36034.1DL
R9681-R9688 R9691-R9698 = R402H16: tolerance: 64.47005.6DL
R9723 R9724 = R805H24: tolerance: 63.R0003.16L
R9742 R9743 = R402H16: tolerance: 64.56R25.6DL
R9744-R9746 R9751 R9873 = R402H16: tolerance: 64.20005.6DL
R9755 R9874 = R402H16: tolerance: 64.30105.6DL
R9756 R9757 = R402H16: tolerance: 64.20R05.6DL
RN801 RN1501-RN1503 RN1901-RN1903 RN5402 RN5407 RN5409 RN5411 = ARES2H16: tolerance: 66.22236.04L
RN2501 RN2502 = SMD-ARES4H18: tolerance: 66.47236.04L
RN3601 RN5404 = SMD-ARES4H18: tolerance: 66.22236.A4L
RN5408 = ARES2H18: tolerance: 66.10336.04L
RN5410 = ARES8-CN24-MUH20: tolerance: 66.10336.08L
RN5601-RN5604 RN6401 = SMD-ARES4H18: tolerance: 66.10236.04L
RN6102 RN9901 = SMD-ARES4H20: tolerance: 66.R0036.04L
SATA0 SATA1 = ABA-SAT-010-K04-U: tolerance: 20.81112.007
SATAP1 = A2501WV2-6P: tolerance: 21.60938.106
SIO1 = LQFP64H63: tolerance: 71.08772.B0G
SPI1 = SKT-SOIC8-092117H235: tolerance: 62.10089.001
TC2203 TC2204 TC2701 TC2704 = ECAP-80D5H493: tolerance: 09.1071D.A89
TP2401 TP2402 = TPAD28: tolerance: ZZ.PAD28.XXX
TP9601 TP9602 = TPAD14-OP: tolerance: ZZ.PAD14.001
TP9905 TP9906 = TPAD24: tolerance: ZZ.PAD24.001
U3RJ1 = PU2B1B5-PRTB: tolerance: 022.10001.0C51
U2402 = SC70-6H44: tolerance: 73.02129.02J
U2502 = SOIC8-1H86: tolerance: 72.25Q64.S01
U2901 U2903 U6510 U6511 = SOT23-8PH36: tolerance: 74.07605.079
U3701-U3703 U3801 = SOT-23-5H56: tolerance: 74.06288.07F
U4301 = SOIC8H69: tolerance: 84.04468.A37
U4601 = QFN28-G3D75H32: tolerance: 71.0850G.003
U4602 = SOIC8H69: tolerance: 72.24C02.0C1
U5401 = SON14J3020-G2610H34: tolerance: 74.22966.093
U6506 = QFN32-G3D6H40: tolerance: 071.02168.0003
U6519 = SOIC8H69: tolerance: 72.24128.G01
USB2F1 = 210-91-05GY21-U: tolerance: 21.62967.105
USB2F2 = A2541WV0-2AX5PA-6T-K: tolerance: 21.62870.205
USB2R1 = SKT-USB12-157183: tolerance: 22.10321.W41
USB3F1 = ABA-USB-050-K07: tolerance: 21.62836.210
VGA1 = DZ11AA1-H5W7-4F: tolerance: 20.20983.015
X1501 = OSC-3225-4P-4H30: tolerance: 82.30071.131
X2101 = OSC-3225-4P-4H36: tolerance: 82.30020.G71
X3501 = OSC-3225-4P-4H36: tolerance: 82.30006.641
X3502 = SMD49-6914-0403H56: tolerance: 82.30001.661
XDP1 = BSH-03001-FDA: tolerance: 20.F0441.060

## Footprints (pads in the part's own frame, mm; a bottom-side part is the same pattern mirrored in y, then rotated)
0R0402-PAD-1
  custom 0.14x0.14 smd: 1(0,0.445) 2(0,-0.445)
0R0603-PAD-1-U
  custom 0.216x0.216 smd: 1(0,0.762) 2(0,-0.762)
0R0805-PAD-1-U
  rect 1.397x1.562 smd: 1(0,0.965)
  rect 1.397x1.569 smd: 2(0,-0.965)
1E450400
  round 1.422 hole 1.016: 1(5.08,-1.27) 2(5.08,1.27) 3(2.54,-1.27) 4(2.54,1.27) 5(0,-1.27) 6(0,1.27) 8(-2.54,1.27) 9(-5.08,-1.27) 10(-5.08,1.27)
  rect 0.025x0.025 smd: 7(-2.54,-1.27)
2DC-G726-Q15
  round 0.254 hole 2.413 unplated: (0,0)
  oval 2.718x1.727 hole 2.007x1.016: 1(0,7.25)
  oval 1.727x2.718 hole 1.016x2.007: 2(-3.1,6.3) 3(-5.2,6.3) 4(3.4,6.3)
  oval 1.727x3.023 hole 1.016x2.311: 5(3.75,-1) 6(-6.15,-1)
2EG38217-D2D-4F
  round 0.254 hole 2.362 unplated: (-73.15,0) (0,0)
  round 1.067 hole 0.711: A1(11.65,-1.25) A2(10.65,-3.25) A3(9.65,-1.25) A4(8.65,-3.25) A5(7.65,-1.25) A6(6.65,-3.25) A7(5.65,-1.25) A8(4.65,-3.25) A9(3.65,-1.25) A10(2.65,-3.25) A11(1.65,-1.25) A12(-1.35,-3.25) A13(-2.35,-1.25) A14(-3.35,-3.25) A15(-4.35,-1.25) A16(-5.35,-3.25) A17(-6.35,-1.25) A18(-7.35,-3.25) A19(-8.35,-1.25) A20(-9.35,-3.25) A21(-10.35,-1.25) A22(-11.35,-3.25) A23(-12.35,-1.25) A24(-13.35,-3.25) A25(-14.35,-1.25) A26(-15.35,-3.25) A27(-16.35,-1.25) A28(-17.35,-3.25) A29(-18.35,-1.25) A30(-19.35,-3.25) A31(-20.35,-1.25) A32(-21.35,-3.25) A33(-22.35,-1.25) A34(-23.35,-3.25) A35(-24.35,-1.25) A36(-25.35,-3.25) A37(-26.35,-1.25) A38(-27.35,-3.25) A39(-28.35,-1.25) A40(-29.35,-3.25) A41(-30.35,-1.25) A42(-31.35,-3.25) A43(-32.35,-1.25) A44(-33.35,-3.25) A45(-34.35,-1.25) A46(-35.35,-3.25) A47(-36.35,-1.25) A48(-37.35,-3.25) A49(-38.35,-1.25) A50(-39.35,-3.25) A51(-40.35,-1.25) A52(-41.35,-3.25) A53(-42.35,-1.25) A54(-43.35,-3.25) A55(-44.35,-1.25) A56(-45.35,-3.25) A57(-46.35,-1.25) A58(-47.35,-3.25) A59(-48.35,-1.25) A60(-49.35,-3.25) A61(-50.35,-1.25) A62(-51.35,-3.25) A63(-52.35,-1.25) A64(-53.35,-3.25) A65(-54.35,-1.25) A66(-55.35,-3.25) A67(-56.35,-1.25) A68(-57.35,-3.25) A69(-58.35,-1.25) A70(-59.35,-3.25) A71(-60.35,-1.25) A72(-61.35,-3.25) A73(-62.35,-1.25) A74(-63.35,-3.25) A75(-64.35,-1.25) A76(-65.35,-3.25) A77(-66.35,-1.25) A78(-67.35,-3.25) A79(-68.35,-1.25) A80(-69.35,-3.25) A81(-70.35,-1.25) A82(-71.35,-3.25) B1(11.65,1.25) B2(10.65,3.25) B3(9.65,1.25) B4(8.65,3.25) B5(7.65,1.25) B6(6.65,3.25) B7(5.65,1.25) B8(4.65,3.25) B9(3.65,1.25) B10(2.65,3.25) B11(1.65,1.25) B12(-1.35,3.25) B13(-2.35,1.25) B14(-3.35,3.25) B15(-4.35,1.25) B16(-5.35,3.25) B17(-6.35,1.25) B18(-7.35,3.25) B19(-8.35,1.25) B20(-9.35,3.25) B21(-10.35,1.25) B22(-11.35,3.25) B23(-12.35,1.25) B24(-13.35,3.25) B25(-14.35,1.25) B26(-15.35,3.25) B27(-16.35,1.25) B28(-17.35,3.25) B29(-18.35,1.25) B30(-19.35,3.25) B31(-20.35,1.25) B32(-21.35,3.25) B33(-22.35,1.25) B34(-23.35,3.25) B35(-24.35,1.25) B36(-25.35,3.25) B37(-26.35,1.25) B38(-27.35,3.25) B39(-28.35,1.25) B40(-29.35,3.25) B41(-30.35,1.25) B42(-31.35,3.25) B43(-32.35,1.25) B44(-33.35,3.25) B45(-34.35,1.25) B46(-35.35,3.25) B47(-36.35,1.25) B48(-37.35,3.25) B49(-38.35,1.25) B50(-39.35,3.25) B51(-40.35,1.25) B52(-41.35,3.25) B53(-42.35,1.25) B54(-43.35,3.25) B55(-44.35,1.25) B56(-45.35,3.25) B57(-46.35,1.25) B58(-47.35,3.25) B59(-48.35,1.25) B60(-49.35,3.25) B61(-50.35,1.25) B62(-51.35,3.25) B63(-52.35,1.25) B64(-53.35,3.25) B65(-54.35,1.25) B66(-55.35,3.25) B67(-56.35,1.25) B68(-57.35,3.25) B69(-58.35,1.25) B70(-59.35,3.25) B71(-60.35,1.25) B72(-61.35,3.25) B73(-62.35,1.25) B74(-63.35,3.25) B75(-64.35,1.25) B76(-65.35,3.25) B77(-66.35,1.25) B78(-67.35,3.25) B79(-68.35,1.25) B80(-69.35,3.25) B81(-70.35,1.25) B82(-71.35,3.25)
21S-91-03GB01
  round 1.422 hole 1.016: 1(-2.54,0) 2(0,0) 3(2.54,0)
210-91-05GY21-U
  rect 0.025x0.025 smd: 1(-5.08,0)
  round 1.422 hole 1.016: 2(-2.54,0) 3(0,0) 4(2.54,0) 5(5.08,0)
220-47-07GB22
  round 1.27 hole 0.889: 1(-6,-1) 2(-6,1) 3(-4,-1) 4(-4,1) 6(-2,1) 7(0,-1) 8(0,1) 9(2,-1) 10(2,1) 11(4,-1) 12(4,1) 13(6,-1) 14(6,1)
  rect 0.025x0.025 smd: 5(-2,-1)
1932208-1
  round 0.254 hole 1.118 unplated: (-33.4,0)
  round 0.254 hole 1.6 unplated: (33.4,0)
  custom 0.114x0.114 smd: 1(31.65,4.1) 2(31.35,-4.1) 3(31.05,4.1) 4(30.751,-4.1) 5(30.45,4.1) 6(30.15,-4.1) 7(29.85,4.1) 8(29.55,-4.1) 9(29.251,4.1) 10(28.95,-4.1) 11(28.65,4.1) 12(28.35,-4.1) 13(28.051,4.1) 14(27.751,-4.1) 15(27.45,4.1) 16(27.15,-4.1) 17(26.851,4.1) 18(26.551,-4.1) 19(26.25,4.1) 20(25.95,-4.1) 21(25.65,4.1) 22(25.35,-4.1) 23(25.051,4.1) 24(24.75,-4.1) 25(24.45,4.1) 26(24.15,-4.1) 27(23.851,4.1) 28(23.55,-4.1) 29(23.25,4.1) 30(22.95,-4.1) 31(22.651,4.1) 32(22.351,-4.1) 33(22.05,4.1) 34(21.75,-4.1) 35(21.451,4.1) 36(21.151,-4.1) 37(20.85,4.1) 38(20.55,-4.1) 39(20.25,4.1) 40(19.95,-4.1) 41(19.65,4.1) 42(19.35,-4.1) 43(19.049,4.1) 44(18.749,-4.1) 45(18.45,4.1) 46(18.15,-4.1) 47(17.85,4.1) 48(17.549,-4.1) 49(17.25,4.1) 50(16.95,-4.1) 51(16.65,4.1) 52(16.349,-4.1) 53(16.049,4.1) 54(15.75,-4.1) 55(15.45,4.1) 56(15.15,-4.1) 57(14.849,4.1) 58(14.549,-4.1) 59(14.25,4.1) 60(13.95,-4.1) 61(13.649,4.1) 62(13.349,-4.1) 63(13.05,4.1) 64(12.75,-4.1) 65(12.45,4.1) 66(12.149,-4.1) 67(11.85,4.1) 68(11.55,-4.1) 69(11.25,4.1) 70(10.95,-4.1) 71(10.649,4.1) 72(10.349,-4.1) 73(7.65,4.1) 74(7.35,-4.1) 75(7.049,4.1) 76(6.749,-4.1) 77(6.45,4.1) 78(6.15,-4.1) 79(5.85,4.1) 80(5.549,-4.1) 81(5.25,4.1) 82(4.95,-4.1) 83(4.65,4.1) 84(4.349,-4.1) 85(4.05,4.1) 86(3.75,-4.1) 87(3.45,4.1) 88(3.15,-4.1) 89(2.849,4.1) 90(2.549,-4.1) 91(2.25,4.1) 92(1.95,-4.1) 93(1.649,4.1) 94(1.349,-4.1) 95(1.05,4.1) 96(0.75,-4.1) 97(0.45,4.1) 98(0.149,-4.1) 99(-0.15,4.1) 100(-0.45,-4.1) 101(-0.75,4.1) 102(-1.051,-4.1) 103(-1.351,4.1) 104(-1.65,-4.1) 105(-1.95,4.1) 106(-2.25,-4.1) 107(-2.551,4.1) 108(-2.851,-4.1) 109(-3.15,4.1) 110(-3.45,-4.1) 111(-3.751,4.1) 112(-4.051,-4.1) 113(-4.35,4.1) 114(-4.65,-4.1) 115(-4.95,4.1) 116(-5.251,-4.1) 117(-5.55,4.1) 118(-5.85,-4.1) 119(-6.15,4.1) 120(-6.451,-4.1) 121(-6.751,4.1) 122(-7.051,-4.1) 123(-7.35,4.1) 124(-7.65,-4.1) 125(-7.951,4.1) 126(-8.251,-4.1) 127(-8.55,4.1) 128(-8.85,-4.1) 129(-9.15,4.1) 130(-9.451,-4.1) 131(-9.75,4.1) 132(-10.05,-4.1) 133(-10.35,4.1) 134(-10.651,-4.1) 135(-10.95,4.1) 136(-11.25,-4.1) 137(-11.55,4.1) 138(-11.85,-4.1) 139(-12.151,4.1) 140(-12.451,-4.1) 141(-12.75,4.1) 142(-13.05,-4.1) 143(-13.351,4.1) 144(-13.651,-4.1) 145(-13.95,4.1) 146(-14.25,-4.1) 147(-14.55,4.1) 148(-14.851,-4.1) 149(-15.15,4.1) 150(-15.45,-4.1) 151(-15.75,4.1) 152(-16.051,-4.1) 153(-16.35,4.1) 154(-16.65,-4.1) 155(-16.95,4.1) 156(-17.25,-4.1) 157(-17.551,4.1) 158(-17.851,-4.1) 159(-18.15,4.1) 160(-18.45,-4.1) 161(-18.751,4.1) 162(-19.051,-4.1) 163(-19.35,4.1) 164(-19.65,-4.1) 165(-19.95,4.1) 166(-20.251,-4.1) 167(-20.55,4.1) 168(-20.85,-4.1) 169(-21.15,4.1) 170(-21.451,-4.1) 171(-21.751,4.1) 172(-22.051,-4.1) 173(-22.35,4.1) 174(-22.65,-4.1) 175(-22.951,4.1) 176(-23.251,-4.1) 177(-23.55,4.1) 178(-23.85,-4.1) 179(-24.151,4.1) 180(-24.451,-4.1) 181(-24.75,4.1) 182(-25.05,-4.1) 183(-25.35,4.1) 184(-25.651,-4.1) 185(-25.95,4.1) 186(-26.25,-4.1) 187(-26.55,4.1) 188(-26.851,-4.1) 189(-27.151,4.1) 190(-27.451,-4.1) 191(-27.75,4.1) 192(-28.05,-4.1) 193(-28.351,4.1) 194(-28.651,-4.1) 195(-28.95,4.1) 196(-29.25,-4.1) 197(-29.55,4.1) 198(-29.851,-4.1) 199(-30.15,4.1) 200(-30.45,-4.1) 201(-30.75,4.1) 202(-31.05,-4.1) 203(-31.349,4.1) 204(-31.649,-4.1)
  rect 3.505x4.597 smd: 205(32.8,12) 206(-32.8,12)
1932210-1
  round 0.254 hole 1.118 unplated: (-33.4,0)
  round 0.254 hole 1.6 unplated: (33.4,0)
  custom 0.114x0.114 smd: 1(31.65,4.1) 2(31.35,-4.1) 3(31.05,4.1) 4(30.75,-4.1) 5(30.45,4.1) 6(30.15,-4.1) 7(29.85,4.1) 8(29.55,-4.1) 9(29.25,4.1) 10(28.95,-4.1) 11(28.65,4.1) 12(28.35,-4.1) 13(28.05,4.1) 14(27.75,-4.1) 15(27.45,4.1) 16(27.15,-4.1) 17(26.85,4.1) 18(26.55,-4.1) 19(26.25,4.1) 20(25.95,-4.1) 21(25.65,4.1) 22(25.35,-4.1) 23(25.05,4.1) 24(24.75,-4.1) 25(24.45,4.1) 26(24.15,-4.1) 27(23.85,4.1) 28(23.55,-4.1) 29(23.25,4.1) 30(22.95,-4.1) 31(22.65,4.1) 32(22.35,-4.1) 33(22.05,4.1) 34(21.75,-4.1) 35(21.45,4.1) 36(21.15,-4.1) 37(20.85,4.1) 38(20.55,-4.1) 39(20.25,4.1) 40(19.95,-4.1) 41(19.65,4.1) 42(19.35,-4.1) 43(19.05,4.1) 44(18.75,-4.1) 45(18.45,4.1) 46(18.15,-4.1) 47(17.85,4.1) 48(17.55,-4.1) 49(17.25,4.1) 50(16.95,-4.1) 51(16.65,4.1) 52(16.35,-4.1) 53(16.05,4.1) 54(15.75,-4.1) 55(15.45,4.1) 56(15.15,-4.1) 57(14.85,4.1) 58(14.55,-4.1) 59(14.25,4.1) 60(13.95,-4.1) 61(13.65,4.1) 62(13.35,-4.1) 63(13.05,4.1) 64(12.75,-4.1) 65(12.45,4.1) 66(12.15,-4.1) 67(11.85,4.1) 68(11.55,-4.1) 69(11.25,4.1) 70(10.95,-4.1) 71(10.65,4.1) 72(10.35,-4.1) 73(7.65,4.1) 74(7.35,-4.1) 75(7.05,4.1) 76(6.75,-4.1) 77(6.45,4.1) 78(6.15,-4.1) 79(5.85,4.1) 80(5.55,-4.1) 81(5.25,4.1) 82(4.95,-4.1) 83(4.65,4.1) 84(4.35,-4.1) 85(4.05,4.1) 86(3.75,-4.1) 87(3.45,4.1) 88(3.15,-4.1) 89(2.85,4.1) 90(2.55,-4.1) 91(2.25,4.1) 92(1.95,-4.1) 93(1.65,4.1) 94(1.35,-4.1) 95(1.05,4.1) 96(0.75,-4.1) 97(0.45,4.1) 98(0.15,-4.1) 99(-0.15,4.1) 100(-0.45,-4.1) 101(-0.75,4.1) 102(-1.05,-4.1) 103(-1.35,4.1) 104(-1.65,-4.1) 105(-1.95,4.1) 106(-2.25,-4.1) 107(-2.55,4.1) 108(-2.85,-4.1) 109(-3.15,4.1) 110(-3.45,-4.1) 111(-3.75,4.1) 112(-4.05,-4.1) 113(-4.35,4.1) 114(-4.65,-4.1) 115(-4.95,4.1) 116(-5.25,-4.1) 117(-5.55,4.1) 118(-5.85,-4.1) 119(-6.15,4.1) 120(-6.45,-4.1) 121(-6.75,4.1) 122(-7.05,-4.1) 123(-7.35,4.1) 124(-7.65,-4.1) 125(-7.95,4.1) 126(-8.25,-4.1) 127(-8.55,4.1) 128(-8.85,-4.1) 129(-9.15,4.1) 130(-9.45,-4.1) 131(-9.75,4.1) 132(-10.05,-4.1) 133(-10.35,4.1) 134(-10.65,-4.1) 135(-10.95,4.1) 136(-11.25,-4.1) 137(-11.55,4.1) 138(-11.85,-4.1) 139(-12.15,4.1) 140(-12.45,-4.1) 141(-12.75,4.1) 142(-13.05,-4.1) 143(-13.35,4.1) 144(-13.65,-4.1) 145(-13.95,4.1) 146(-14.25,-4.1) 147(-14.55,4.1) 148(-14.85,-4.1) 149(-15.15,4.1) 150(-15.45,-4.1) 151(-15.75,4.1) 152(-16.05,-4.1) 153(-16.35,4.1) 154(-16.65,-4.1) 155(-16.95,4.1) 156(-17.25,-4.1) 157(-17.55,4.1) 158(-17.85,-4.1) 159(-18.15,4.1) 160(-18.45,-4.1) 161(-18.75,4.1) 162(-19.05,-4.1) 163(-19.35,4.1) 164(-19.65,-4.1) 165(-19.95,4.1) 166(-20.25,-4.1) 167(-20.55,4.1) 168(-20.85,-4.1) 169(-21.15,4.1) 170(-21.45,-4.1) 171(-21.75,4.1) 172(-22.05,-4.1) 173(-22.35,4.1) 174(-22.65,-4.1) 175(-22.95,4.1) 176(-23.25,-4.1) 177(-23.55,4.1) 178(-23.85,-4.1) 179(-24.15,4.1) 180(-24.45,-4.1) 181(-24.75,4.1) 182(-25.05,-4.1) 183(-25.35,4.1) 184(-25.65,-4.1) 185(-25.95,4.1) 186(-26.25,-4.1) 187(-26.55,4.1) 188(-26.85,-4.1) 189(-27.15,4.1) 190(-27.45,-4.1) 191(-27.75,4.1) 192(-28.05,-4.1) 193(-28.35,4.1) 194(-28.65,-4.1) 195(-28.95,4.1) 196(-29.25,-4.1) 197(-29.55,4.1) 198(-29.85,-4.1) 199(-30.15,4.1) 200(-30.45,-4.1) 201(-30.75,4.1) 202(-31.05,-4.1) 203(-31.35,4.1) 204(-31.65,-4.1)
  rect 4.496x4.597 smd: 205(37.452,12) 206(-37.452,12)
A2501WV2-6P
  round 1.397 hole 0.991: 1(6.25,0) 2(3.75,0) 3(1.25,0) 4(-1.25,0) 5(-3.75,0) 6(-6.25,0)
A2541WV0-1EX2PA-6T
  round 1.397 hole 0.991: 1(-1.27,0) 2(1.27,0)
A2541WV0-2AX5PA-6T-K
  rect 0.025x0.025 smd: 1(5.08,-1.27)
  round 1.422 hole 1.016: 2(5.08,1.27) 3(2.54,-1.27) 4(2.54,1.27) 5(0,-1.27) 6(0,1.27) 7(-2.54,-1.27) 8(-2.54,1.27) 9(-5.08,-1.27) 10(-5.08,1.27)
A2543WV2-3P
  round 1.422 hole 1.016: 1(2.54,0) 2(0,0) 3(-2.54,0)
AAA-BAT-029-K01
  round 1.727 hole 1.321: 1(11.8,0) 2(-8.2,0)
AAA-DDR-109-P06
  round 0.254 hole 1.6 unplated: (-33.4,0)
  round 0.254 hole 1.118 unplated: (33.4,0)
  custom 0.114x0.114 smd: 1(-31.65,-4.1) 2(-31.35,4.1) 3(-31.05,-4.1) 4(-30.75,4.1) 5(-30.45,-4.1) 6(-30.15,4.1) 7(-29.85,-4.1) 8(-29.55,4.1) 9(-29.25,-4.1) 10(-28.95,4.1) 11(-28.65,-4.1) 12(-28.35,4.1) 13(-28.05,-4.1) 14(-27.75,4.1) 15(-27.45,-4.1) 16(-27.15,4.1) 17(-26.85,-4.1) 18(-26.55,4.1) 19(-26.25,-4.1) 20(-25.95,4.1) 21(-25.65,-4.1) 22(-25.35,4.1) 23(-25.05,-4.1) 24(-24.75,4.1) 25(-24.45,-4.1) 26(-24.15,4.1) 27(-23.85,-4.1) 28(-23.55,4.1) 29(-23.25,-4.1) 30(-22.95,4.1) 31(-22.65,-4.1) 32(-22.35,4.1) 33(-22.05,-4.1) 34(-21.75,4.1) 35(-21.45,-4.1) 36(-21.15,4.1) 37(-20.85,-4.1) 38(-20.55,4.1) 39(-20.25,-4.1) 40(-19.95,4.1) 41(-19.65,-4.1) 42(-19.35,4.1) 43(-19.05,-4.1) 44(-18.75,4.1) 45(-18.45,-4.1) 46(-18.15,4.1) 47(-17.85,-4.1) 48(-17.55,4.1) 49(-17.25,-4.1) 50(-16.95,4.1) 51(-16.65,-4.1) 52(-16.35,4.1) 53(-16.05,-4.1) 54(-15.75,4.1) 55(-15.45,-4.1) 56(-15.15,4.1) 57(-14.85,-4.1) 58(-14.55,4.1) 59(-14.25,-4.1) 60(-13.95,4.1) 61(-13.65,-4.1) 62(-13.35,4.1) 63(-13.05,-4.1) 64(-12.75,4.1) 65(-12.45,-4.1) 66(-12.15,4.1) 67(-11.85,-4.1) 68(-11.55,4.1) 69(-11.25,-4.1) 70(-10.95,4.1) 71(-10.65,-4.1) 72(-10.35,4.1) 73(-7.65,-4.1) 74(-7.35,4.1) 75(-7.05,-4.1) 76(-6.75,4.1) 77(-6.45,-4.1) 78(-6.15,4.1) 79(-5.85,-4.1) 80(-5.55,4.1) 81(-5.25,-4.1) 82(-4.95,4.1) 83(-4.65,-4.1) 84(-4.35,4.1) 85(-4.05,-4.1) 86(-3.75,4.1) 87(-3.45,-4.1) 88(-3.15,4.1) 89(-2.85,-4.1) 90(-2.55,4.1) 91(-2.25,-4.1) 92(-1.95,4.1) 93(-1.65,-4.1) 94(-1.35,4.1) 95(-1.05,-4.1) 96(-0.75,4.1) 97(-0.45,-4.1) 98(-0.15,4.1) 99(0.15,-4.1) 100(0.45,4.1) 101(0.75,-4.1) 102(1.05,4.1) 103(1.35,-4.1) 104(1.65,4.1) 105(1.95,-4.1) 106(2.25,4.1) 107(2.55,-4.1) 108(2.85,4.1) 109(3.15,-4.1) 110(3.45,4.1) 111(3.75,-4.1) 112(4.05,4.1) 113(4.35,-4.1) 114(4.65,4.1) 115(4.95,-4.1) 116(5.25,4.1) 117(5.55,-4.1) 118(5.85,4.1) 119(6.15,-4.1) 120(6.45,4.1) 121(6.75,-4.1) 122(7.05,4.1) 123(7.35,-4.1) 124(7.65,4.1) 125(7.95,-4.1) 126(8.25,4.1) 127(8.55,-4.1) 128(8.85,4.1) 129(9.15,-4.1) 130(9.45,4.1) 131(9.75,-4.1) 132(10.05,4.1) 133(10.35,-4.1) 134(10.65,4.1) 135(10.95,-4.1) 136(11.25,4.1) 137(11.55,-4.1) 138(11.85,4.1) 139(12.15,-4.1) 140(12.45,4.1) 141(12.75,-4.1) 142(13.05,4.1) 143(13.35,-4.1) 144(13.65,4.1) 145(13.95,-4.1) 146(14.25,4.1) 147(14.55,-4.1) 148(14.85,4.1) 149(15.15,-4.1) 150(15.45,4.1) 151(15.75,-4.1) 152(16.05,4.1) 153(16.35,-4.1) 154(16.65,4.1) 155(16.95,-4.1) 156(17.25,4.1) 157(17.55,-4.1) 158(17.85,4.1) 159(18.15,-4.1) 160(18.45,4.1) 161(18.75,-4.1) 162(19.05,4.1) 163(19.35,-4.1) 164(19.65,4.1) 165(19.95,-4.1) 166(20.25,4.1) 167(20.55,-4.1) 168(20.85,4.1) 169(21.15,-4.1) 170(21.45,4.1) 171(21.75,-4.1) 172(22.05,4.1) 173(22.35,-4.1) 174(22.65,4.1) 175(22.95,-4.1) 176(23.25,4.1) 177(23.55,-4.1) 178(23.85,4.1) 179(24.15,-4.1) 180(24.45,4.1) 181(24.75,-4.1) 182(25.05,4.1) 183(25.35,-4.1) 184(25.65,4.1) 185(25.95,-4.1) 186(26.25,4.1) 187(26.55,-4.1) 188(26.85,4.1) 189(27.15,-4.1) 190(27.45,4.1) 191(27.75,-4.1) 192(28.05,4.1) 193(28.35,-4.1) 194(28.65,4.1) 195(28.95,-4.1) 196(29.25,4.1) 197(29.55,-4.1) 198(29.85,4.1) 199(30.15,-4.1) 200(30.45,4.1) 201(30.75,-4.1) 202(31.05,4.1) 203(31.35,-4.1) 204(31.65,4.1)
  rect 3.505x4.597 smd: 205(-32.8,12) 206(32.8,12)
ABA-JAK-028-K03
  round 0.254 hole 2.311 unplated: (0,0)
  round 1.422 hole 1.016: 1(0,-3.8) 2(-5,-3.8) 3(-2.5,-3.8) 4(2.5,-3.8) 5(5,-3.8) 22(-3.75,-8.8) 23(-1.25,-8.8) 24(1.25,-8.8) 25(3.75,-8.8) 32(-3.75,-13.8) 33(-1.25,-13.8) 34(1.25,-13.8) 35(3.75,-13.8)
  round 2.718 hole 2.311: G1(6.04,0) G2(-6.04,0) G3(6.04,-11.3) G4(-6.04,-11.3)
ABA-SAT-010-K04-U
  round 1.118 hole 0.762: 1(-3.81,-0.5) 4(0,-0.5) 7(3.81,-0.5)
  oval 1.041x1.168 hole 0.762: 2(-2.54,0.5) 3(-1.27,0.5) 5(1.27,0.5) 6(2.54,0.5)
  round 1.778 hole 1.372: 8(-6.48,0) 9(6.48,0)
ABA-USB-050-K07
  round 1.168 hole 0.813: 1(-9,1) 2(-7,1) 3(-5,1) 4(-3,1) 5(-1,1) 6(1,1) 7(3,1) 8(5,1) 9(7,1) 10(9,1) 11(9,-1) 12(7,-1) 13(5,-1) 14(3,-1) 15(1,-1) 16(-1,-1) 17(-3,-1) 18(-5,-1) 19(-7,-1)
  rect 0.025x0.025 smd: 20(-9,-1)
AC-1205G-N1LF-U
  round 1.321 hole 0.914: 1(0,3.25) 2(0,-3.25)
ARES2H16
  rect 0.356x0.66 smd: 1(-0.325,-0.599) 2(0.325,-0.599) 3(0.325,0.599) 4(-0.325,0.599)
ARES2H18
  rect 0.356x0.66 smd: 1(-0.325,-0.599) 2(0.325,-0.599) 3(0.325,0.599) 4(-0.325,0.599)
ARES8-CN24-MUH20
  rect 0.61x0.66 smd: 1(-0.9,-0.486) 4(0.9,-0.486) 5(0.9,0.486) 8(-0.9,0.486)
  rect 0.305x0.66 smd: 2(-0.25,-0.486) 3(0.25,-0.486) 6(0.25,0.486) 7(-0.25,0.486)
AS0BC21-S40BE-7H
  round 0.254 hole 1.168 unplated: (-10,0)
  round 0.254 hole 1.651 unplated: (10,0)
  rect 0.305x1.549 smd: 1(-9.25,5.275) 2(-9,-2.275) 3(-8.75,5.275) 4(-8.5,-2.275) 5(-8.25,5.275) 6(-8,-2.275) 7(-7.75,5.275) 8(-7.5,-2.275) 9(-7.25,5.275) 10(-7,-2.275) 11(-6.75,5.275) 12(-6.5,-2.275) 13(-6.25,5.275) 14(-6,-2.275) 15(-5.75,5.275) 16(-5.5,-2.275) 17(-5.25,5.275) 18(-5,-2.275) 19(-4.75,5.275) 20(-4.5,-2.275) 21(-4.25,5.275) 22(-4,-2.275) 23(-3.75,5.275) 32(-1.5,-2.275) 33(-1.25,5.275) 34(-1,-2.275) 35(-0.75,5.275) 36(-0.5,-2.275) 37(-0.25,5.275) 38(0,-2.275) 39(0.25,5.275) 40(0.5,-2.275) 41(0.75,5.275) 42(1,-2.275) 43(1.25,5.275) 44(1.5,-2.275) 45(1.75,5.275) 46(2,-2.275) 47(2.25,5.275) 48(2.5,-2.275) 49(2.75,5.275) 50(3,-2.275) 51(3.25,5.275) 52(3.5,-2.275) 53(3.75,5.275) 54(4,-2.275) 55(4.25,5.275) 56(4.5,-2.275) 57(4.75,5.275) 58(5,-2.275) 59(5.25,5.275) 60(5.5,-2.275) 61(5.75,5.275) 62(6,-2.275) 63(6.25,5.275) 64(6.5,-2.275) 65(6.75,5.275) 66(7,-2.275) 67(7.25,5.275) 68(7.5,-2.275) 69(7.75,5.275) 70(8,-2.275) 71(8.25,5.275) 72(8.5,-2.275) 73(8.75,5.275) 74(9,-2.275) 75(9.25,5.275)
  rect 1.194x2.743 smd: 76(-10.35,4.5) 77(10.35,4.5)
BGA1170M2725H57
  round 0.508 smd: A3(11.951,-11.814) A52(-12.383,-11.814) B2(12.383,-11.383) B53(-12.814,-11.383) BH1(12.814,11.383) BH53(-12.814,11.383) BJ2(12.383,11.814) BJ52(-12.383,11.814) C1(12.814,-10.951)
  round 0.406 smd: A5(11.17,-11.814) A6(10.447,-11.814) A49(-10.992,-11.814) A51(-11.773,-11.814) B52(-12.225,-11.225) BE1(12.814,9.992) BE53(-12.814,9.992) BG1(12.814,10.773) BG53(-12.814,10.773) BH2(12.225,11.225) BH52(-12.225,11.225) BJ3(11.773,11.814) BJ5(10.992,11.814) BJ49(-10.992,11.814) BJ51(-11.773,11.814) C53(-12.814,-10.773) E1(12.814,-10.17) E53(-12.814,-9.992) F1(12.814,-9.447)
  round 0.356 smd: A7(9.748,-11.814) A9(8.836,-11.814) A47(-9.621,-11.814) A48(-10.294,-11.814) B4(11.632,-11.238) B5(11.038,-11.222) B6(10.445,-11.221) B8(9.258,-11.224) B46(-9.258,-11.224) B48(-10.445,-11.221) B49(-11.038,-11.222) B50(-11.632,-11.238) BC1(12.814,8.621) BC2(12.246,8.852) BC52(-12.246,8.852) BC53(-12.814,8.621) BD1(12.814,9.294) BD2(12.221,9.445) BD52(-12.221,9.445) BD53(-12.814,9.294) BE2(12.222,10.038) BE52(-12.222,10.038) BF2(12.238,10.632) BF52(-12.238,10.632) BG3(11.644,10.644) BG51(-11.644,10.644) BH4(11.632,11.238) BH5(11.038,11.222) BH6(10.445,11.221) BH8(9.258,11.224) BH46(-9.258,11.224) BH48(-10.445,11.221) BH49(-11.038,11.222) BH50(-11.632,11.238) BJ6(10.294,11.814) BJ7(9.621,11.814) BJ47(-9.621,11.814) BJ48(-10.294,11.814) C3(11.644,-10.644) C51(-11.644,-10.644) D2(12.238,-10.632) D52(-12.238,-10.632) E2(12.222,-10.038) E52(-12.222,-10.038) F2(12.221,-9.445) F52(-12.221,-9.445) F53(-12.814,-9.294) G1(12.814,-8.679) G2(12.246,-8.852) G52(-12.246,-8.852) G53(-12.814,-8.621) J1(12.814,-7.816)
  oval 0.254x0.343 smd: A11(7.774,-11.814) A13(6.803,-11.814) A15(5.831,-11.814) A17(4.859,-11.814) A19(3.887,-11.814) A21(2.915,-11.814) A23(1.944,-11.814) A25(0.972,-11.814) A27(0,-11.814) A29(-0.972,-11.814) A31(-1.944,-11.814) A33(-2.915,-11.814) A35(-3.887,-11.814) A37(-4.859,-11.814) A39(-5.831,-11.814) A41(-6.803,-11.814) A43(-7.774,-11.814) A45(-8.746,-11.814) BJ9(8.746,11.814) BJ11(7.774,11.814) BJ13(6.803,11.814) BJ15(5.831,11.814) BJ17(4.859,11.814) BJ19(3.887,11.814) BJ21(2.915,11.814) BJ23(1.944,11.814) BJ25(0.972,11.814) BJ27(0,11.814) BJ29(-0.972,11.814) BJ31(-1.944,11.814) BJ33(-2.915,11.814) BJ35(-3.887,11.814) BJ37(-4.859,11.814) BJ39(-5.831,11.814) BJ41(-6.803,11.814) BJ43(-7.774,11.814) BJ45(-8.746,11.814)
  oval 0.343x0.254 smd: AA1(12.814,-1.944) AA53(-12.814,-1.944) AC1(12.814,-0.972) AC53(-12.814,-0.972) AE1(12.814,0) AE53(-12.814,0) AG1(12.814,0.972) AG53(-12.814,0.972) AJ1(12.814,1.944) AJ53(-12.814,1.944) AL1(12.814,2.915) AL53(-12.814,2.915) AN1(12.814,3.887) AN53(-12.814,3.887) AR1(12.814,4.859) AR53(-12.814,4.859) AU1(12.814,5.831) AU53(-12.814,5.831) AW1(12.814,6.803) AW53(-12.814,6.803) BA1(12.814,7.774) BA53(-12.814,7.774) J53(-12.814,-7.774) L1(12.814,-6.803) L53(-12.814,-6.803) N1(12.814,-5.831) N53(-12.814,-5.831) R1(12.814,-4.859) R53(-12.814,-4.859) U1(12.814,-3.887) U53(-12.814,-3.887) W1(12.814,-2.915) W53(-12.814,-2.915)
  round 0.279 smd: AA3(12.071,-1.944) AA51(-12.071,-1.944) AB2(12.429,-1.458) AB3(11.73,-1.458) AB51(-11.73,-1.458) AB52(-12.429,-1.458) AC3(12.071,-0.972) AC51(-12.071,-0.972) AD2(12.429,-0.486) AD3(11.715,-0.48) AD51(-11.715,-0.48) AD52(-12.429,-0.486) AE3(12.071,0) AE4(11.366,0) AE50(-11.366,0) AE51(-12.071,0) AF2(12.429,0.486) AF3(11.715,0.48) AF51(-11.715,0.48) AF52(-12.429,0.486) AG3(12.071,0.972) AG51(-12.071,0.972) AH2(12.429,1.458) AH3(11.73,1.458) AH51(-11.73,1.458) AH52(-12.429,1.458) AJ3(12.071,1.944) AJ51(-12.071,1.944) AK2(12.429,2.43) AK3(11.73,2.43) AK51(-11.73,2.43) AK52(-12.429,2.43) AL3(12.071,2.915) AL51(-12.071,2.915) AM2(12.429,3.401) AM3(11.73,3.401) AM51(-11.73,3.401) AM52(-12.429,3.401) AN3(12.071,3.887) AN51(-12.071,3.887) AP2(12.429,4.373) AP3(11.73,4.373) AP51(-11.73,4.373) AP52(-12.429,4.373) AR3(12.071,4.859) AR51(-12.071,4.859) AT2(12.429,5.345) AT3(11.73,5.345) AT51(-11.73,5.345) AT52(-12.429,5.345) AU3(12.071,5.831) AU51(-12.071,5.831) AV2(12.429,6.317) AV3(11.73,6.317) AV51(-11.73,6.317) AV52(-12.429,6.317) AW3(12.071,6.803) AW51(-12.071,6.803) AY2(12.429,7.289) AY3(11.73,7.289) AY51(-11.73,7.289) AY52(-12.429,7.289) B10(8.26,-11.429) B12(7.289,-11.429) B14(6.317,-11.429) B16(5.345,-11.429) B18(4.373,-11.429) B20(3.401,-11.429) B22(2.43,-11.429) B24(1.458,-11.429) B26(0.486,-11.429) B28(-0.486,-11.429) B30(-1.458,-11.429) B32(-2.43,-11.429) B34(-3.401,-11.429) B36(-4.373,-11.429) B38(-5.345,-11.429) B40(-6.317,-11.429) B42(-7.289,-11.429) B44(-8.26,-11.429) BA3(12.071,7.774) BA51(-12.071,7.774) BB3(11.929,8.351) BB51(-11.929,8.351) BF27(0,10.366) BG9(8.698,11.028) BG11(7.774,11.071) BG12(7.289,10.73) BG13(6.803,11.071) BG14(6.317,10.73) BG15(5.831,11.071) BG16(5.345,10.73) BG17(4.859,11.071) BG18(4.373,10.73) BG19(3.887,11.071) BG20(3.401,10.73) BG21(2.915,11.071) BG22(2.43,10.73) BG23(1.944,11.071) BG24(1.458,10.73) BG25(0.972,11.071) BG26(0.48,10.715) BG27(0,11.071) BG28(-0.48,10.715) BG29(-0.972,11.071) BG30(-1.458,10.73) BG31(-1.944,11.071) BG32(-2.43,10.73) BG33(-2.915,11.071) BG34(-3.401,10.73) BG35(-3.887,11.071) BG36(-4.373,10.73) BG37(-4.859,11.071) BG38(-5.345,10.73) BG39(-5.831,11.071) BG40(-6.317,10.73) BG41(-6.803,11.071) BG42(-7.289,10.73) BG43(-7.774,11.071) BG45(-8.698,11.028) BH10(8.26,11.429) BH12(7.289,11.429) BH14(6.317,11.429) BH16(5.345,11.429) BH18(4.373,11.429) BH20(3.401,11.429) BH22(2.43,11.429) BH24(1.458,11.429) BH26(0.486,11.429) BH28(-0.486,11.429) BH30(-1.458,11.429) BH32(-2.43,11.429) BH34(-3.401,11.429) BH36(-4.373,11.429) BH38(-5.345,11.429) BH40(-6.317,11.429) BH42(-7.289,11.429) BH44(-8.26,11.429) C9(8.698,-11.028) C11(7.774,-11.071) C12(7.289,-10.73) C13(6.803,-11.071) C14(6.317,-10.73) C15(5.831,-11.071) C16(5.345,-10.73) C17(4.859,-11.071) C18(4.373,-10.73) C19(3.887,-11.071) C20(3.401,-10.73) C21(2.915,-11.071) C22(2.43,-10.73) C23(1.944,-11.071) C24(1.458,-10.73) C25(0.972,-11.071) C26(0.48,-10.715) C27(0,-11.071) C28(-0.48,-10.715) C29(-0.972,-11.071) C30(-1.458,-10.73) C31(-1.944,-11.071) C32(-2.43,-10.73) C33(-2.915,-11.071) C34(-3.401,-10.73) C35(-3.887,-11.071) C36(-4.373,-10.73) C37(-4.859,-11.071) C38(-5.345,-10.73) C39(-5.831,-11.071) C40(-6.317,-10.73) C41(-6.803,-11.071) C42(-7.289,-10.73) C43(-7.774,-11.071) C45(-8.698,-11.028) D27(0,-10.366) H3(11.929,-8.351) H51(-11.929,-8.351) J3(12.071,-7.774) J51(-12.071,-7.774) K2(12.429,-7.289) K3(11.73,-7.289) K51(-11.73,-7.289) K52(-12.429,-7.289) L3(12.071,-6.803) L51(-12.071,-6.803) M2(12.429,-6.317) M3(11.73,-6.317) M51(-11.73,-6.317) M52(-12.429,-6.317) N3(12.071,-5.831) N51(-12.071,-5.831) P2(12.429,-5.345) P3(11.73,-5.345) P51(-11.73,-5.345) P52(-12.429,-5.345) R3(12.071,-4.859) R51(-12.071,-4.859) T2(12.429,-4.373) T3(11.73,-4.373) T51(-11.73,-4.373) T52(-12.429,-4.373) U3(12.071,-3.887) U51(-12.071,-3.887) V2(12.429,-3.401) V3(11.73,-3.401) V51(-11.73,-3.401) V52(-12.429,-3.401) W3(12.071,-2.915) W51(-12.071,-2.915) Y2(12.429,-2.43) Y3(11.73,-2.43) Y51(-11.73,-2.43) Y52(-12.429,-2.43)
  round 0.33 smd: AA16(5.307,-1.961) AA18(4.549,-1.961) AA19(3.791,-1.961) AA21(3.033,-1.961) AA22(2.275,-1.961) AA24(1.516,-1.961) AA25(0.758,-1.961) AA27(0,-1.961) AA29(-0.758,-1.961) AA30(-1.516,-1.961) AA32(-2.275,-1.961) AA33(-3.033,-1.961) AA35(-3.791,-1.961) AA36(-4.549,-1.961) AA38(-5.307,-1.961) AC16(5.307,-1.177) AC18(4.549,-1.177) AC19(3.791,-1.177) AC21(3.033,-1.177) AC22(2.275,-1.177) AC24(1.516,-1.177) AC25(0.758,-1.177) AC27(0,-1.177) AC29(-0.758,-1.177) AC30(-1.516,-1.177) AC32(-2.275,-1.177) AC33(-3.033,-1.177) AC35(-3.791,-1.177) AC36(-4.549,-1.177) AC38(-5.307,-1.177) AD16(5.307,-0.392) AD18(4.549,-0.392) AD19(3.791,-0.392) AD21(3.033,-0.392) AD22(2.275,-0.392) AD24(1.516,-0.392) AD25(0.758,-0.392) AD27(0,-0.392) AD29(-0.758,-0.392) AD30(-1.516,-0.392) AD32(-2.275,-0.392) AD33(-3.033,-0.392) AD35(-3.791,-0.392) AD36(-4.549,-0.392) AD38(-5.307,-0.392) AF16(5.307,0.392) AF18(4.549,0.392) AF19(3.791,0.392) AF21(3.033,0.392) AF22(2.275,0.392) AF24(1.516,0.392) AF25(0.758,0.392) AF27(0,0.392) AF29(-0.758,0.392) AF30(-1.516,0.392) AF32(-2.275,0.392) AF33(-3.033,0.392) AF35(-3.791,0.392) AF36(-4.549,0.392) AF38(-5.307,0.392) AG16(5.307,1.177) AG18(4.549,1.177) AG19(3.791,1.177) AG21(3.033,1.177) AG22(2.275,1.177) AG24(1.516,1.177) AG25(0.758,1.177) AG27(0,1.177) AG29(-0.758,1.177) AG30(-1.516,1.177) AG32(-2.275,1.177) AG33(-3.033,1.177) AG35(-3.791,1.177) AG36(-4.549,1.177) AG38(-5.307,1.177) AJ16(5.307,1.961) AJ18(4.549,1.961) AJ19(3.791,1.961) AJ21(3.033,1.961) AJ22(2.275,1.961) AJ24(1.516,1.961) AJ25(0.758,1.961) AJ27(0,1.961) AJ29(-0.758,1.961) AJ30(-1.516,1.961) AJ32(-2.275,1.961) AJ33(-3.033,1.961) AJ35(-3.791,1.961) AJ36(-4.549,1.961) AJ38(-5.307,1.961) AK16(5.307,2.745) AK18(4.549,2.745) AK19(3.791,2.745) AK21(3.033,2.745) AK22(2.275,2.745) AK24(1.516,2.745) AK25(0.758,2.745) AK27(0,2.745) AK29(-0.758,2.745) AK30(-1.516,2.745) AK32(-2.275,2.745) AK33(-3.033,2.745) AK35(-3.791,2.745) AK36(-4.549,2.745) AK38(-5.307,2.745) AM16(5.307,3.53) AM18(4.549,3.53) AM19(3.791,3.53) AM21(3.033,3.53) AM22(2.275,3.53) AM24(1.516,3.53) AM25(0.758,3.53) AM27(0,3.53) AM29(-0.758,3.53) AM30(-1.516,3.53) AM32(-2.275,3.53) AM33(-3.033,3.53) AM35(-3.791,3.53) AM36(-4.549,3.53) AM38(-5.307,3.53) AN16(5.307,4.314) AN18(4.549,4.314) AN19(3.791,4.314) AN21(3.033,4.314) AN22(2.275,4.314) AN24(1.516,4.314) AN25(0.758,4.314) AN27(0,4.314) AN29(-0.758,4.314) AN30(-1.516,4.314) AN32(-2.275,4.314) AN33(-3.033,4.314) AN35(-3.791,4.314) AN36(-4.549,4.314) AN38(-5.307,4.314) U16(5.307,-4.314) U18(4.549,-4.314) U19(3.791,-4.314) U21(3.033,-4.314) U22(2.275,-4.314) U24(1.516,-4.314) U25(0.758,-4.314) U27(0,-4.314) U29(-0.758,-4.314) U30(-1.516,-4.314) U32(-2.275,-4.314) U33(-3.033,-4.314) U35(-3.791,-4.314) U36(-4.549,-4.314) U38(-5.307,-4.314) V16(5.307,-3.53) V18(4.549,-3.53) V19(3.791,-3.53) V21(3.033,-3.53) V22(2.275,-3.53) V24(1.516,-3.53) V25(0.758,-3.53) V27(0,-3.53) V29(-0.758,-3.53) V30(-1.516,-3.53) V32(-2.275,-3.53) V33(-3.033,-3.53) V35(-3.791,-3.53) V36(-4.549,-3.53) V38(-5.307,-3.53) Y16(5.307,-2.745) Y18(4.549,-2.745) Y19(3.791,-2.745) Y21(3.033,-2.745) Y22(2.275,-2.745) Y24(1.516,-2.745) Y25(0.758,-2.745) Y27(0,-2.745) Y29(-0.758,-2.745) Y30(-1.516,-2.745) Y32(-2.275,-2.745) Y33(-3.033,-2.745) Y35(-3.791,-2.745) Y36(-4.549,-2.745) Y38(-5.307,-2.745)
  round 0.305 smd: AB4(11.137,-1.448) AB6(10.463,-1.448) AB7(9.752,-1.448) AB9(9.041,-1.448) AB10(8.33,-1.448) AB12(7.618,-1.448) AB13(6.907,-1.448) AB14(6.196,-1.448) AB40(-6.196,-1.448) AB41(-6.907,-1.448) AB42(-7.618,-1.448) AB44(-8.33,-1.448) AB45(-9.041,-1.448) AB47(-9.752,-1.448) AB48(-10.463,-1.448) AB50(-11.137,-1.448) AD4(10.995,-0.463) AD6(10.404,-0.525) AD7(9.752,-0.475) AD9(9.041,-0.475) AD10(8.33,-0.475) AD12(7.618,-0.475) AD13(6.907,-0.475) AD14(6.196,-0.475) AD40(-6.196,-0.475) AD41(-6.907,-0.475) AD42(-7.618,-0.475) AD44(-8.33,-0.475) AD45(-9.041,-0.475) AD47(-9.752,-0.475) AD48(-10.404,-0.525) AD50(-10.995,-0.463) AE6(10.108,0) AE8(9.396,0) AE9(8.685,0) AE11(7.974,0) AE12(7.263,0) AE14(6.552,0) AE40(-6.552,0) AE42(-7.263,0) AE43(-7.974,0) AE45(-8.685,0) AE46(-9.396,0) AE48(-10.108,0) AF4(10.995,0.463) AF6(10.404,0.525) AF7(9.752,0.475) AF9(9.041,0.475) AF10(8.33,0.475) AF12(7.618,0.475) AF13(6.907,0.475) AF14(6.196,0.475) AF40(-6.196,0.475) AF41(-6.907,0.475) AF42(-7.618,0.475) AF44(-8.33,0.475) AF45(-9.041,0.475) AF47(-9.752,0.475) AF48(-10.404,0.525) AF50(-10.995,0.463) AH4(11.137,1.448) AH6(10.463,1.448) AH7(9.752,1.448) AH9(9.041,1.448) AH10(8.33,1.448) AH12(7.618,1.448) AH13(6.907,1.448) AH14(6.196,1.448) AH40(-6.196,1.448) AH41(-6.907,1.448) AH42(-7.618,1.448) AH44(-8.33,1.448) AH45(-9.041,1.448) AH47(-9.752,1.448) AH48(-10.463,1.448) AH50(-11.137,1.448) AK4(11.137,2.439) AK6(10.463,2.439) AK7(9.752,2.439) AK9(9.041,2.439) AK10(8.33,2.439) AK12(7.618,2.439) AK13(6.907,2.439) AK14(6.196,2.439) AK40(-6.196,2.439) AK41(-6.907,2.439) AK42(-7.618,2.439) AK44(-8.33,2.439) AK45(-9.041,2.439) AK47(-9.752,2.439) AK48(-10.463,2.439) AK50(-11.137,2.439) AM4(11.137,3.386) AM6(10.463,3.412) AM7(9.752,3.412) AM9(9.041,3.412) AM10(8.33,3.412) AM12(7.618,3.412) AM13(6.907,3.412) AM14(6.196,3.412) AM40(-6.196,3.412) AM41(-6.907,3.412) AM42(-7.618,3.412) AM44(-8.33,3.412) AM45(-9.041,3.412) AM47(-9.752,3.412) AM48(-10.463,3.412) AM50(-11.137,3.386) AN5(10.819,3.887) AN6(10.108,3.887) AN8(9.396,3.887) AN9(8.685,3.887) AN11(7.974,3.887) AN12(7.263,3.887) AN14(6.552,3.887) AN40(-6.552,3.887) AN42(-7.263,3.887) AN43(-7.974,3.887) AN45(-8.685,3.887) AN46(-9.396,3.887) AN48(-10.108,3.887) AN49(-10.819,3.887) AP4(11.137,4.388) AP6(10.463,4.362) AP7(9.752,4.362) AP9(9.041,4.362) AP10(8.33,4.362) AP12(7.618,4.362) AP13(6.907,4.362) AP14(6.196,4.362) AP40(-6.196,4.362) AP41(-6.907,4.362) AP42(-7.618,4.362) AP44(-8.33,4.362) AP45(-9.041,4.362) AP47(-9.752,4.362) AP48(-10.463,4.362) AP50(-11.137,4.388) AT4(11.137,5.336) AT6(10.463,5.336) AT7(9.752,5.336) AT9(9.041,5.336) AT10(8.33,5.336) AT12(7.618,5.336) AT13(6.907,5.336) AT14(6.305,5.336) AT16(5.336,5.196) AT18(4.362,5.196) AT19(3.887,5.552) AT20(3.412,5.196) AT22(2.439,5.196) AT24(1.448,5.196) AT26(0.475,5.196) AT27(0,5.552) AT28(-0.475,5.196) AT30(-1.448,5.196) AT32(-2.439,5.196) AT34(-3.412,5.196) AT35(-3.887,5.552) AT36(-4.362,5.196) AT38(-5.336,5.196) AT40(-6.305,5.336) AT41(-6.907,5.336) AT42(-7.618,5.336) AT44(-8.33,5.336) AT45(-9.041,5.336) AT47(-9.752,5.336) AT48(-10.463,5.336) AT50(-11.137,5.336) AU16(5.336,5.907) AU18(4.362,5.907) AU20(3.412,5.907) AU22(2.439,5.907) AU24(1.448,5.907) AU26(0.475,5.907) AU28(-0.475,5.907) AU30(-1.448,5.907) AU32(-2.439,5.907) AU34(-3.412,5.907) AU36(-4.362,5.907) AU38(-5.336,5.907) AV4(11.137,6.326) AV6(10.463,6.326) AV7(9.752,6.326) AV9(9.041,6.326) AV10(8.33,6.326) AV12(7.618,6.326) AV13(6.907,6.326) AV14(6.326,6.446) AV16(5.336,6.618) AV18(4.362,6.618) AV19(3.887,6.263) AV20(3.412,6.618) AV22(2.439,6.618) AV24(1.448,6.618) AV26(0.475,6.618) AV27(0,6.263) AV28(-0.475,6.618) AV30(-1.448,6.618) AV32(-2.439,6.618) AV34(-3.412,6.618) AV35(-3.887,6.263) AV36(-4.362,6.618) AV38(-5.336,6.618) AV40(-6.326,6.446) AV41(-6.907,6.326) AV42(-7.618,6.326) AV44(-8.33,6.326) AV45(-9.041,6.326) AV47(-9.752,6.326) AV48(-10.463,6.326) AV50(-11.137,6.326) AW13(6.751,6.915) AW19(3.887,6.974) AW27(0,6.974) AW35(-3.887,6.974) AW41(-6.751,6.915) AY4(11.137,7.317) AY6(10.463,7.317) AY7(9.752,7.317) AY9(9.041,7.317) AY10(8.33,7.317) AY12(7.317,7.34) AY14(6.326,7.33) AY16(5.336,7.33) AY18(4.362,7.33) AY20(3.412,7.33) AY22(2.439,7.33) AY24(1.448,7.33) AY26(0.475,7.33) AY28(-0.475,7.33) AY30(-1.448,7.33) AY32(-2.439,7.33) AY34(-3.412,7.33) AY36(-4.362,7.33) AY38(-5.336,7.33) AY40(-6.326,7.33) AY42(-7.317,7.34) AY44(-8.33,7.317) AY45(-9.041,7.317) AY47(-9.752,7.317) AY48(-10.463,7.317) AY50(-11.137,7.317) B7(9.852,-11.23) B47(-9.852,-11.23) BA12(7.317,8.041) BA14(6.326,8.041) BA16(5.336,8.041) BA18(4.362,8.041) BA19(3.887,7.685) BA20(3.412,8.041) BA22(2.439,8.041) BA24(1.448,8.041) BA26(0.475,8.041) BA27(0,7.685) BA28(-0.475,8.041) BA30(-1.448,8.041) BA32(-2.439,8.041) BA34(-3.412,8.041) BA35(-3.887,7.685) BA36(-4.362,8.041) BA38(-5.336,8.041) BA40(-6.326,8.041) BA42(-7.317,8.041) BB4(11.258,8.307) BB5(10.547,8.307) BB7(9.835,8.307) BB8(9.124,8.307) BB10(8.307,8.17) BB19(3.887,8.396) BB27(0,8.396) BB35(-3.887,8.396) BB44(-8.307,8.17) BB46(-9.124,8.307) BB47(-9.835,8.307) BB49(-10.547,8.307) BB50(-11.258,8.307) BC10(8.307,8.764) BC12(7.317,8.752) BC14(6.326,8.752) BC16(5.336,8.752) BC18(4.362,8.752) BC20(3.412,8.752) BC22(2.439,8.752) BC24(1.448,8.752) BC26(0.475,8.752) BC28(-0.475,8.752) BC30(-1.448,8.752) BC32(-2.439,8.752) BC34(-3.412,8.752) BC36(-4.362,8.752) BC38(-5.336,8.752) BC40(-6.326,8.752) BC42(-7.317,8.752) BC44(-8.307,8.764) BD5(10.565,9.302) BD7(9.712,9.302) BD10(8.307,9.457) BD12(7.317,9.463) BD14(6.326,9.463) BD16(5.336,9.463) BD18(4.362,9.463) BD19(3.887,9.108) BD20(3.412,9.463) BD22(2.439,9.463) BD24(1.448,9.463) BD26(0.525,9.404) BD27(0,9.108) BD28(-0.525,9.404) BD30(-1.448,9.463) BD32(-2.439,9.463) BD34(-3.412,9.463) BD35(-3.887,9.108) BD36(-4.362,9.463) BD38(-5.336,9.463) BD40(-6.326,9.463) BD42(-7.317,9.463) BD44(-8.307,9.457) BD47(-9.712,9.302) BD49(-10.565,9.302) BE3(11.643,9.58) BE8(9.32,9.747) BE19(3.887,9.819) BE35(-3.887,9.819) BE46(-9.32,9.747) BE51(-11.643,9.58) BF4(11.163,10.163) BF6(10.113,10.238) BF10(8.307,10.168) BF12(7.317,10.137) BF14(6.326,10.137) BF16(5.336,10.137) BF18(4.388,10.137) BF20(3.386,10.137) BF22(2.439,10.137) BF24(1.448,10.137) BF26(0.463,9.995) BF28(-0.463,9.995) BF30(-1.448,10.137) BF32(-2.439,10.137) BF34(-3.386,10.137) BF36(-4.388,10.137) BF38(-5.336,10.137) BF40(-6.326,10.137) BF42(-7.317,10.137) BF44(-8.307,10.168) BF48(-10.113,10.238) BF50(-11.163,10.163) BG5(10.58,10.643) BG7(9.553,10.709) BG47(-9.553,10.709) BG49(-10.58,10.643) BH7(9.852,11.23) BH47(-9.852,11.23) C5(10.58,-10.643) C7(9.553,-10.709) C47(-9.553,-10.709) C49(-10.58,-10.643) D4(11.163,-10.163) D6(10.113,-10.238) D10(8.307,-10.168) D12(7.317,-10.137) D14(6.326,-10.137) D16(5.336,-10.137) D18(4.388,-10.137) D20(3.386,-10.137) D22(2.439,-10.137) D24(1.448,-10.137) D26(0.463,-9.995) D28(-0.463,-9.995) D30(-1.448,-10.137) D32(-2.439,-10.137) D34(-3.386,-10.137) D36(-4.388,-10.137) D38(-5.336,-10.137) D40(-6.326,-10.137) D42(-7.317,-10.137) D44(-8.307,-10.168) D48(-10.113,-10.238) D50(-11.163,-10.163) E3(11.643,-9.58) E8(9.32,-9.747) E19(3.887,-9.819) E35(-3.887,-9.819) E46(-9.32,-9.747) E51(-11.643,-9.58) F5(10.565,-9.302) F7(9.712,-9.302) F10(8.307,-9.457) F12(7.317,-9.463) F14(6.326,-9.463) F16(5.336,-9.463) F18(4.362,-9.463) F19(3.887,-9.108) F20(3.412,-9.463) F22(2.439,-9.463) F24(1.448,-9.463) F26(0.525,-9.404) F27(0,-9.108) F28(-0.525,-9.404) F30(-1.448,-9.463) F32(-2.439,-9.463) F34(-3.412,-9.463) F35(-3.887,-9.108) F36(-4.362,-9.463) F38(-5.336,-9.463) F40(-6.326,-9.463) F42(-7.317,-9.463) F44(-8.307,-9.457) F47(-9.712,-9.302) F49(-10.565,-9.302) G10(8.307,-8.764) G12(7.317,-8.752) G14(6.326,-8.752) G16(5.336,-8.752) G18(4.362,-8.752) G20(3.412,-8.752) G22(2.439,-8.752) G24(1.448,-8.752) G26(0.475,-8.752) G28(-0.475,-8.752) G30(-1.448,-8.752) G32(-2.439,-8.752) G34(-3.412,-8.752) G36(-4.362,-8.752) G38(-5.336,-8.752) G40(-6.326,-8.752) G42(-7.317,-8.752) G44(-8.307,-8.764) H4(11.258,-8.307) H5(10.547,-8.307) H7(9.835,-8.307) H8(9.124,-8.307) H10(8.307,-8.17) H19(3.887,-8.396) H27(0,-8.396) H35(-3.887,-8.396) H44(-8.307,-8.17) H46(-9.124,-8.307) H47(-9.835,-8.307) H49(-10.547,-8.307) H50(-11.258,-8.307) J12(7.317,-8.041) J14(6.326,-8.041) J16(5.336,-8.041) J18(4.362,-8.041) J19(3.887,-7.685) J20(3.412,-8.041) J22(2.439,-8.041) J24(1.448,-8.041) J26(0.475,-8.041) J27(0,-7.685) J28(-0.475,-8.041) J30(-1.448,-8.041) J32(-2.439,-8.041) J34(-3.412,-8.041) J35(-3.887,-7.685) J36(-4.362,-8.041) J38(-5.336,-8.041) J40(-6.326,-8.041) J42(-7.317,-8.041) K4(11.137,-7.317) K6(10.463,-7.317) K7(9.752,-7.317) K9(9.041,-7.317) K10(8.33,-7.317) K12(7.317,-7.34) K14(6.326,-7.33) K16(5.336,-7.33) K18(4.362,-7.33) K20(3.412,-7.33) K22(2.439,-7.33) K24(1.448,-7.33) K26(0.475,-7.33) K28(-0.475,-7.33) K30(-1.448,-7.33) K32(-2.439,-7.33) K34(-3.412,-7.33) K36(-4.362,-7.33) K38(-5.336,-7.33) K40(-6.326,-7.33) K42(-7.317,-7.34) K44(-8.33,-7.317) K45(-9.041,-7.317) K47(-9.752,-7.317) K48(-10.463,-7.317) K50(-11.137,-7.317) L13(6.751,-6.915) L19(3.887,-6.974) L27(0,-6.974) L35(-3.887,-6.974) L41(-6.751,-6.915) M4(11.137,-6.326) M6(10.463,-6.326) M7(9.752,-6.326) M9(9.041,-6.326) M10(8.33,-6.326) M12(7.618,-6.326) M13(6.907,-6.326) M14(6.326,-6.446) M16(5.336,-6.618) M18(4.362,-6.618) M19(3.887,-6.263) M20(3.412,-6.618) M22(2.439,-6.618) M24(1.448,-6.618) M26(0.475,-6.618) M27(0,-6.263) M28(-0.475,-6.618) M30(-1.448,-6.618) M32(-2.439,-6.618) M34(-3.412,-6.618) M35(-3.887,-6.263) M36(-4.362,-6.618) M38(-5.336,-6.618) M40(-6.326,-6.446) M41(-6.907,-6.326) M42(-7.618,-6.326) M44(-8.33,-6.326) M45(-9.041,-6.326) M47(-9.752,-6.326) M48(-10.463,-6.326) M50(-11.137,-6.326) N16(5.336,-5.907) N18(4.362,-5.907) N20(3.412,-5.907) N22(2.439,-5.907) N24(1.448,-5.907) N26(0.475,-5.907) N28(-0.475,-5.907) N30(-1.448,-5.907) N32(-2.439,-5.907) N34(-3.412,-5.907) N36(-4.362,-5.907) N38(-5.336,-5.907) P4(11.137,-5.336) P6(10.463,-5.336) P7(9.752,-5.336) P9(9.041,-5.336) P10(8.33,-5.336) P12(7.618,-5.336) P13(6.907,-5.336) P14(6.305,-5.336) P16(5.336,-5.196) P18(4.362,-5.196) P19(3.887,-5.552) P20(3.412,-5.196) P22(2.439,-5.196) P24(1.448,-5.196) P26(0.475,-5.196) P27(0,-5.552) P28(-0.475,-5.196) P30(-1.448,-5.196) P32(-2.439,-5.196) P34(-3.412,-5.196) P35(-3.887,-5.552) P36(-4.362,-5.196) P38(-5.336,-5.196) P40(-6.305,-5.336) P41(-6.907,-5.336) P42(-7.618,-5.336) P44(-8.33,-5.336) P45(-9.041,-5.336) P47(-9.752,-5.336) P48(-10.463,-5.336) P50(-11.137,-5.336) T4(11.137,-4.388) T6(10.463,-4.362) T7(9.752,-4.362) T9(9.041,-4.362) T10(8.33,-4.362) T12(7.618,-4.362) T13(6.907,-4.362) T14(6.196,-4.362) T40(-6.196,-4.362) T41(-6.907,-4.362) T42(-7.618,-4.362) T44(-8.33,-4.362) T45(-9.041,-4.362) T47(-9.752,-4.362) T48(-10.463,-4.362) T50(-11.137,-4.388) U5(10.819,-3.887) U6(10.108,-3.887) U8(9.396,-3.887) U9(8.685,-3.887) U11(7.974,-3.887) U12(7.263,-3.887) U14(6.552,-3.887) U40(-6.552,-3.887) U42(-7.263,-3.887) U43(-7.974,-3.887) U45(-8.685,-3.887) U46(-9.396,-3.887) U48(-10.108,-3.887) U49(-10.819,-3.887) V4(11.137,-3.386) V6(10.463,-3.412) V7(9.752,-3.412) V9(9.041,-3.412) V10(8.33,-3.412) V12(7.618,-3.412) V13(6.907,-3.412) V14(6.196,-3.412) V40(-6.196,-3.412) V41(-6.907,-3.412) V42(-7.618,-3.412) V44(-8.33,-3.412) V45(-9.041,-3.412) V47(-9.752,-3.412) V48(-10.463,-3.412) V50(-11.137,-3.386) Y4(11.137,-2.439) Y6(10.463,-2.439) Y7(9.752,-2.439) Y9(9.041,-2.439) Y10(8.33,-2.439) Y12(7.618,-2.439) Y13(6.907,-2.439) Y14(6.196,-2.439) Y40(-6.196,-2.439) Y41(-6.907,-2.439) Y42(-7.618,-2.439) Y44(-8.33,-2.439) Y45(-9.041,-2.439) Y47(-9.752,-2.439) Y48(-10.463,-2.439) Y50(-11.137,-2.439)
